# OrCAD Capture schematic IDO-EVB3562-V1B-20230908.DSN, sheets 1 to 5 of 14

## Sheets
1 P11. Power: size A4
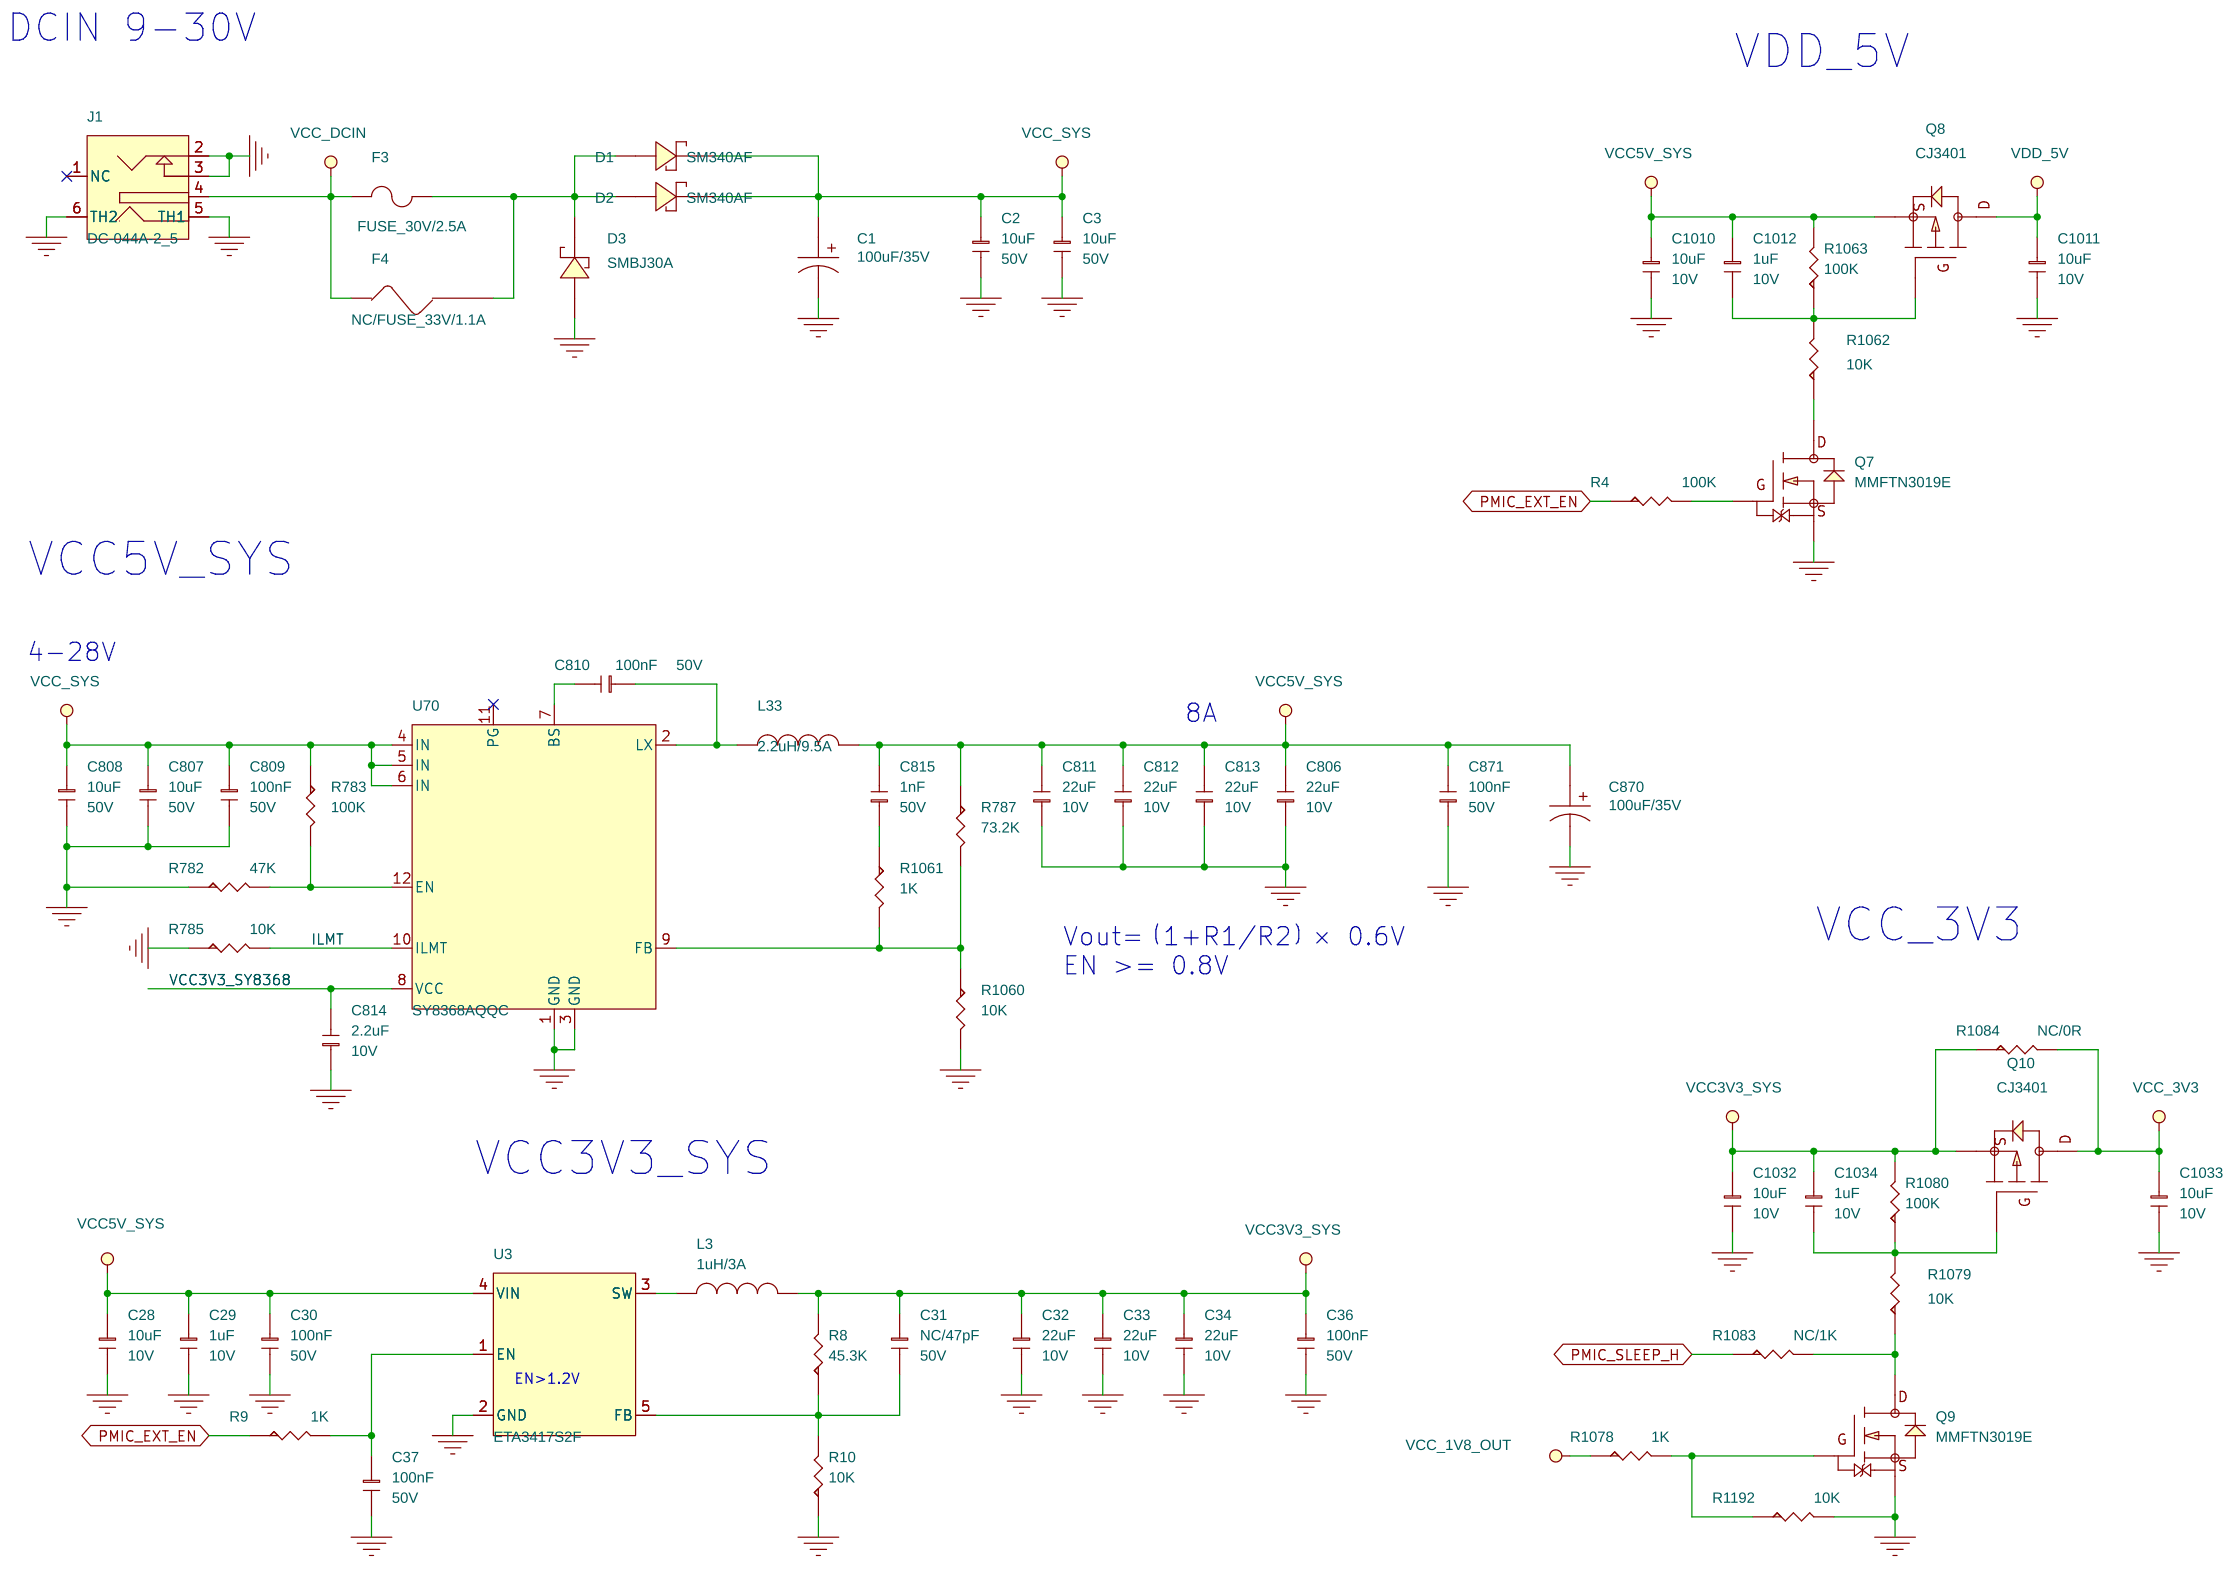
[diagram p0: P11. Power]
2 P12. SOM3562: size A2
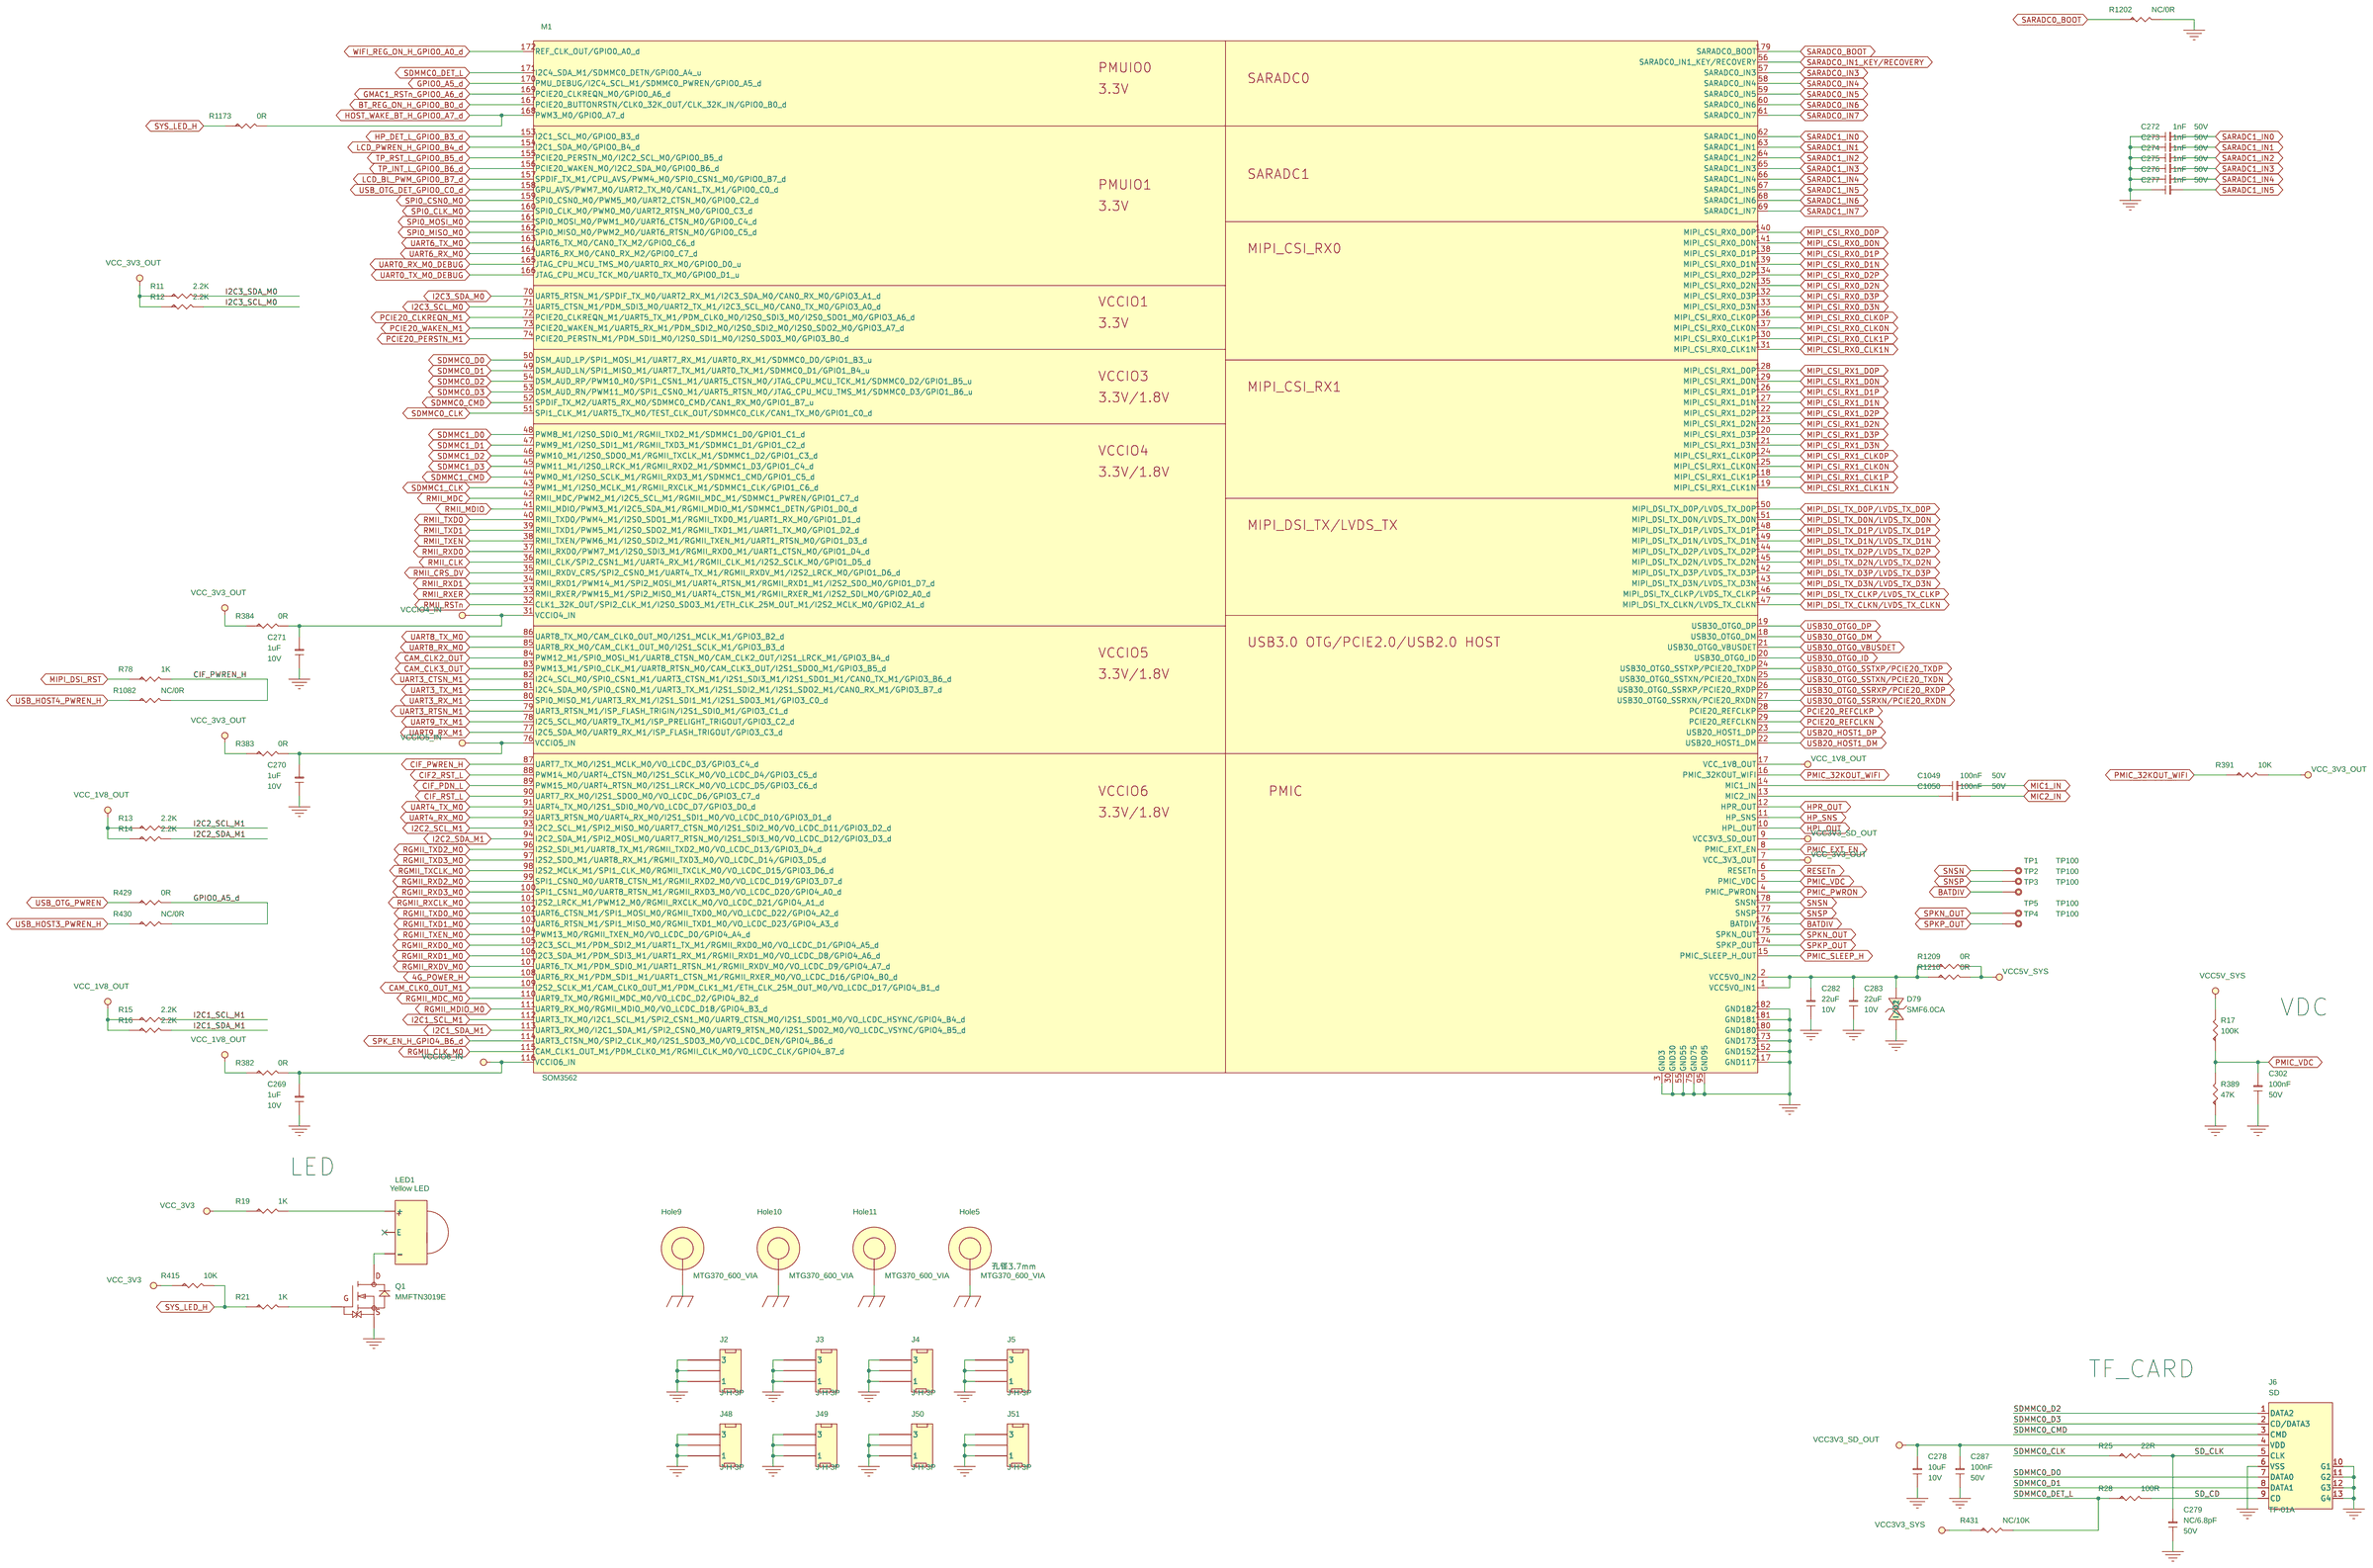
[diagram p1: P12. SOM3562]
3 P13.USB_HUB-FE1.1: size A3; title: IDO-SBC3566-V1B; note: USB_HUB-FE1.1
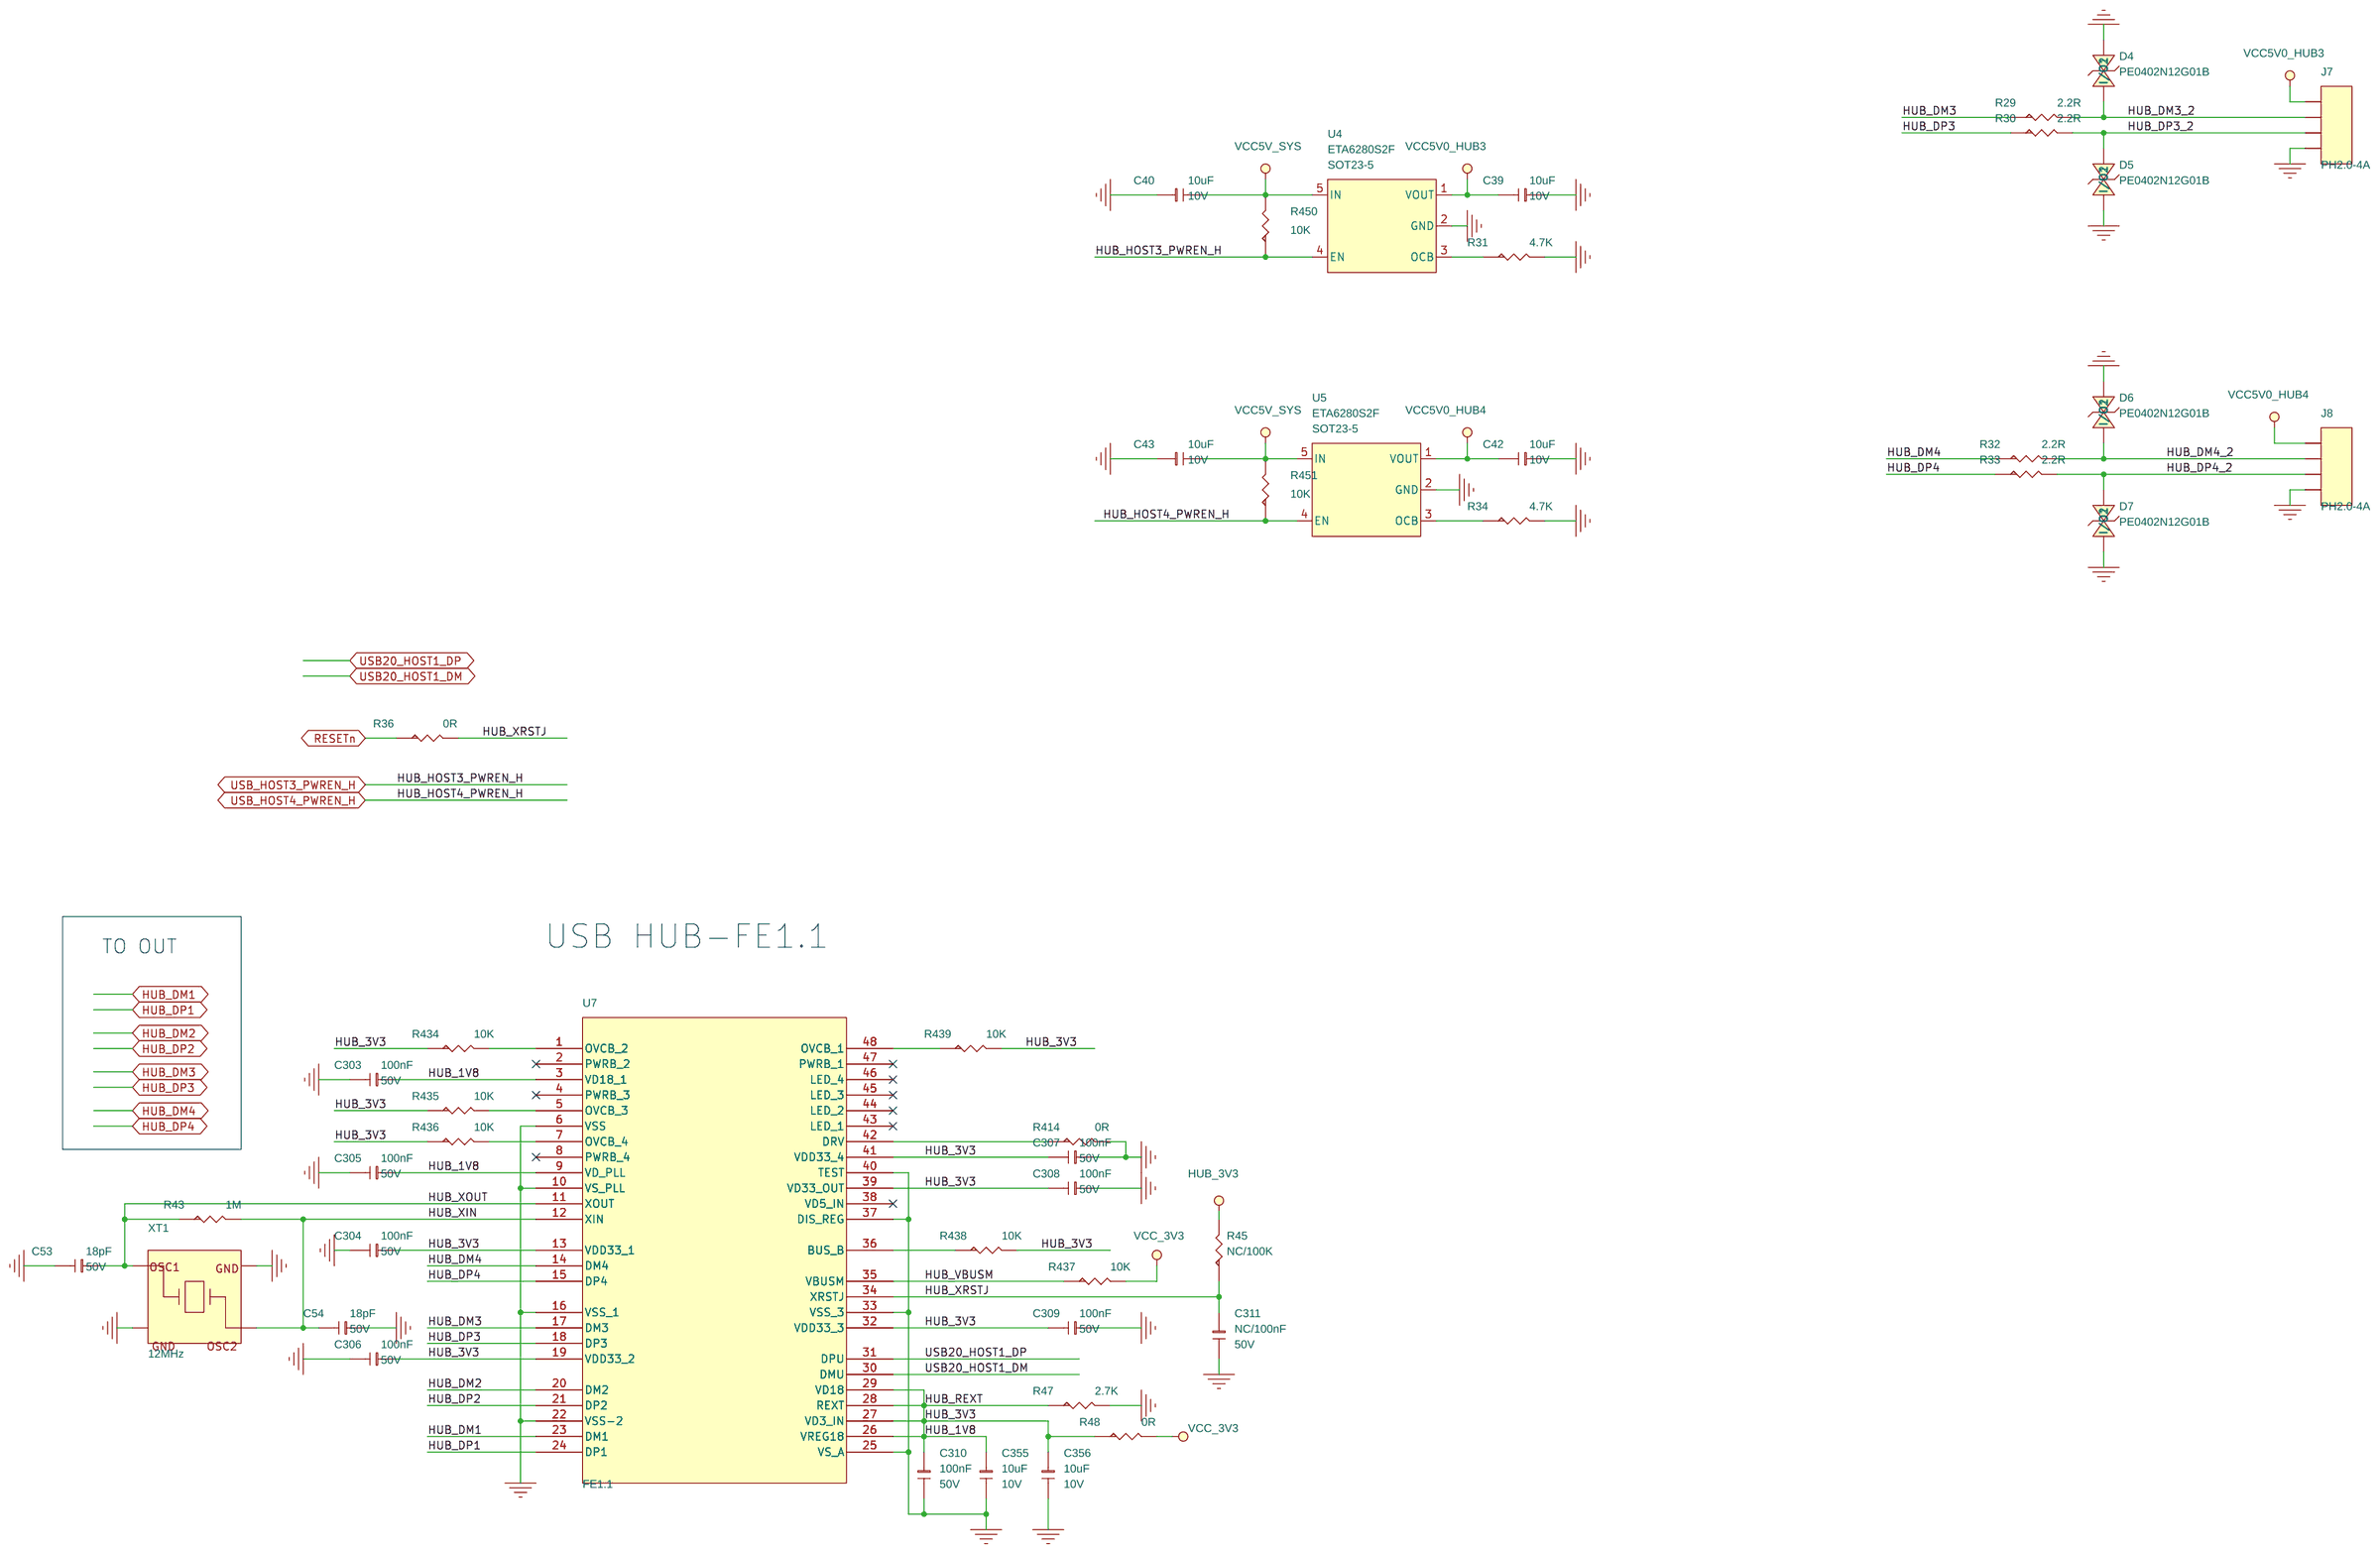
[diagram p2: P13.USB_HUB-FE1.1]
4 P14. 4G-MINI_PCIE: size A3; title: IDO-SBC3566-V1B; note: 4G/5G-MINI_PCIE
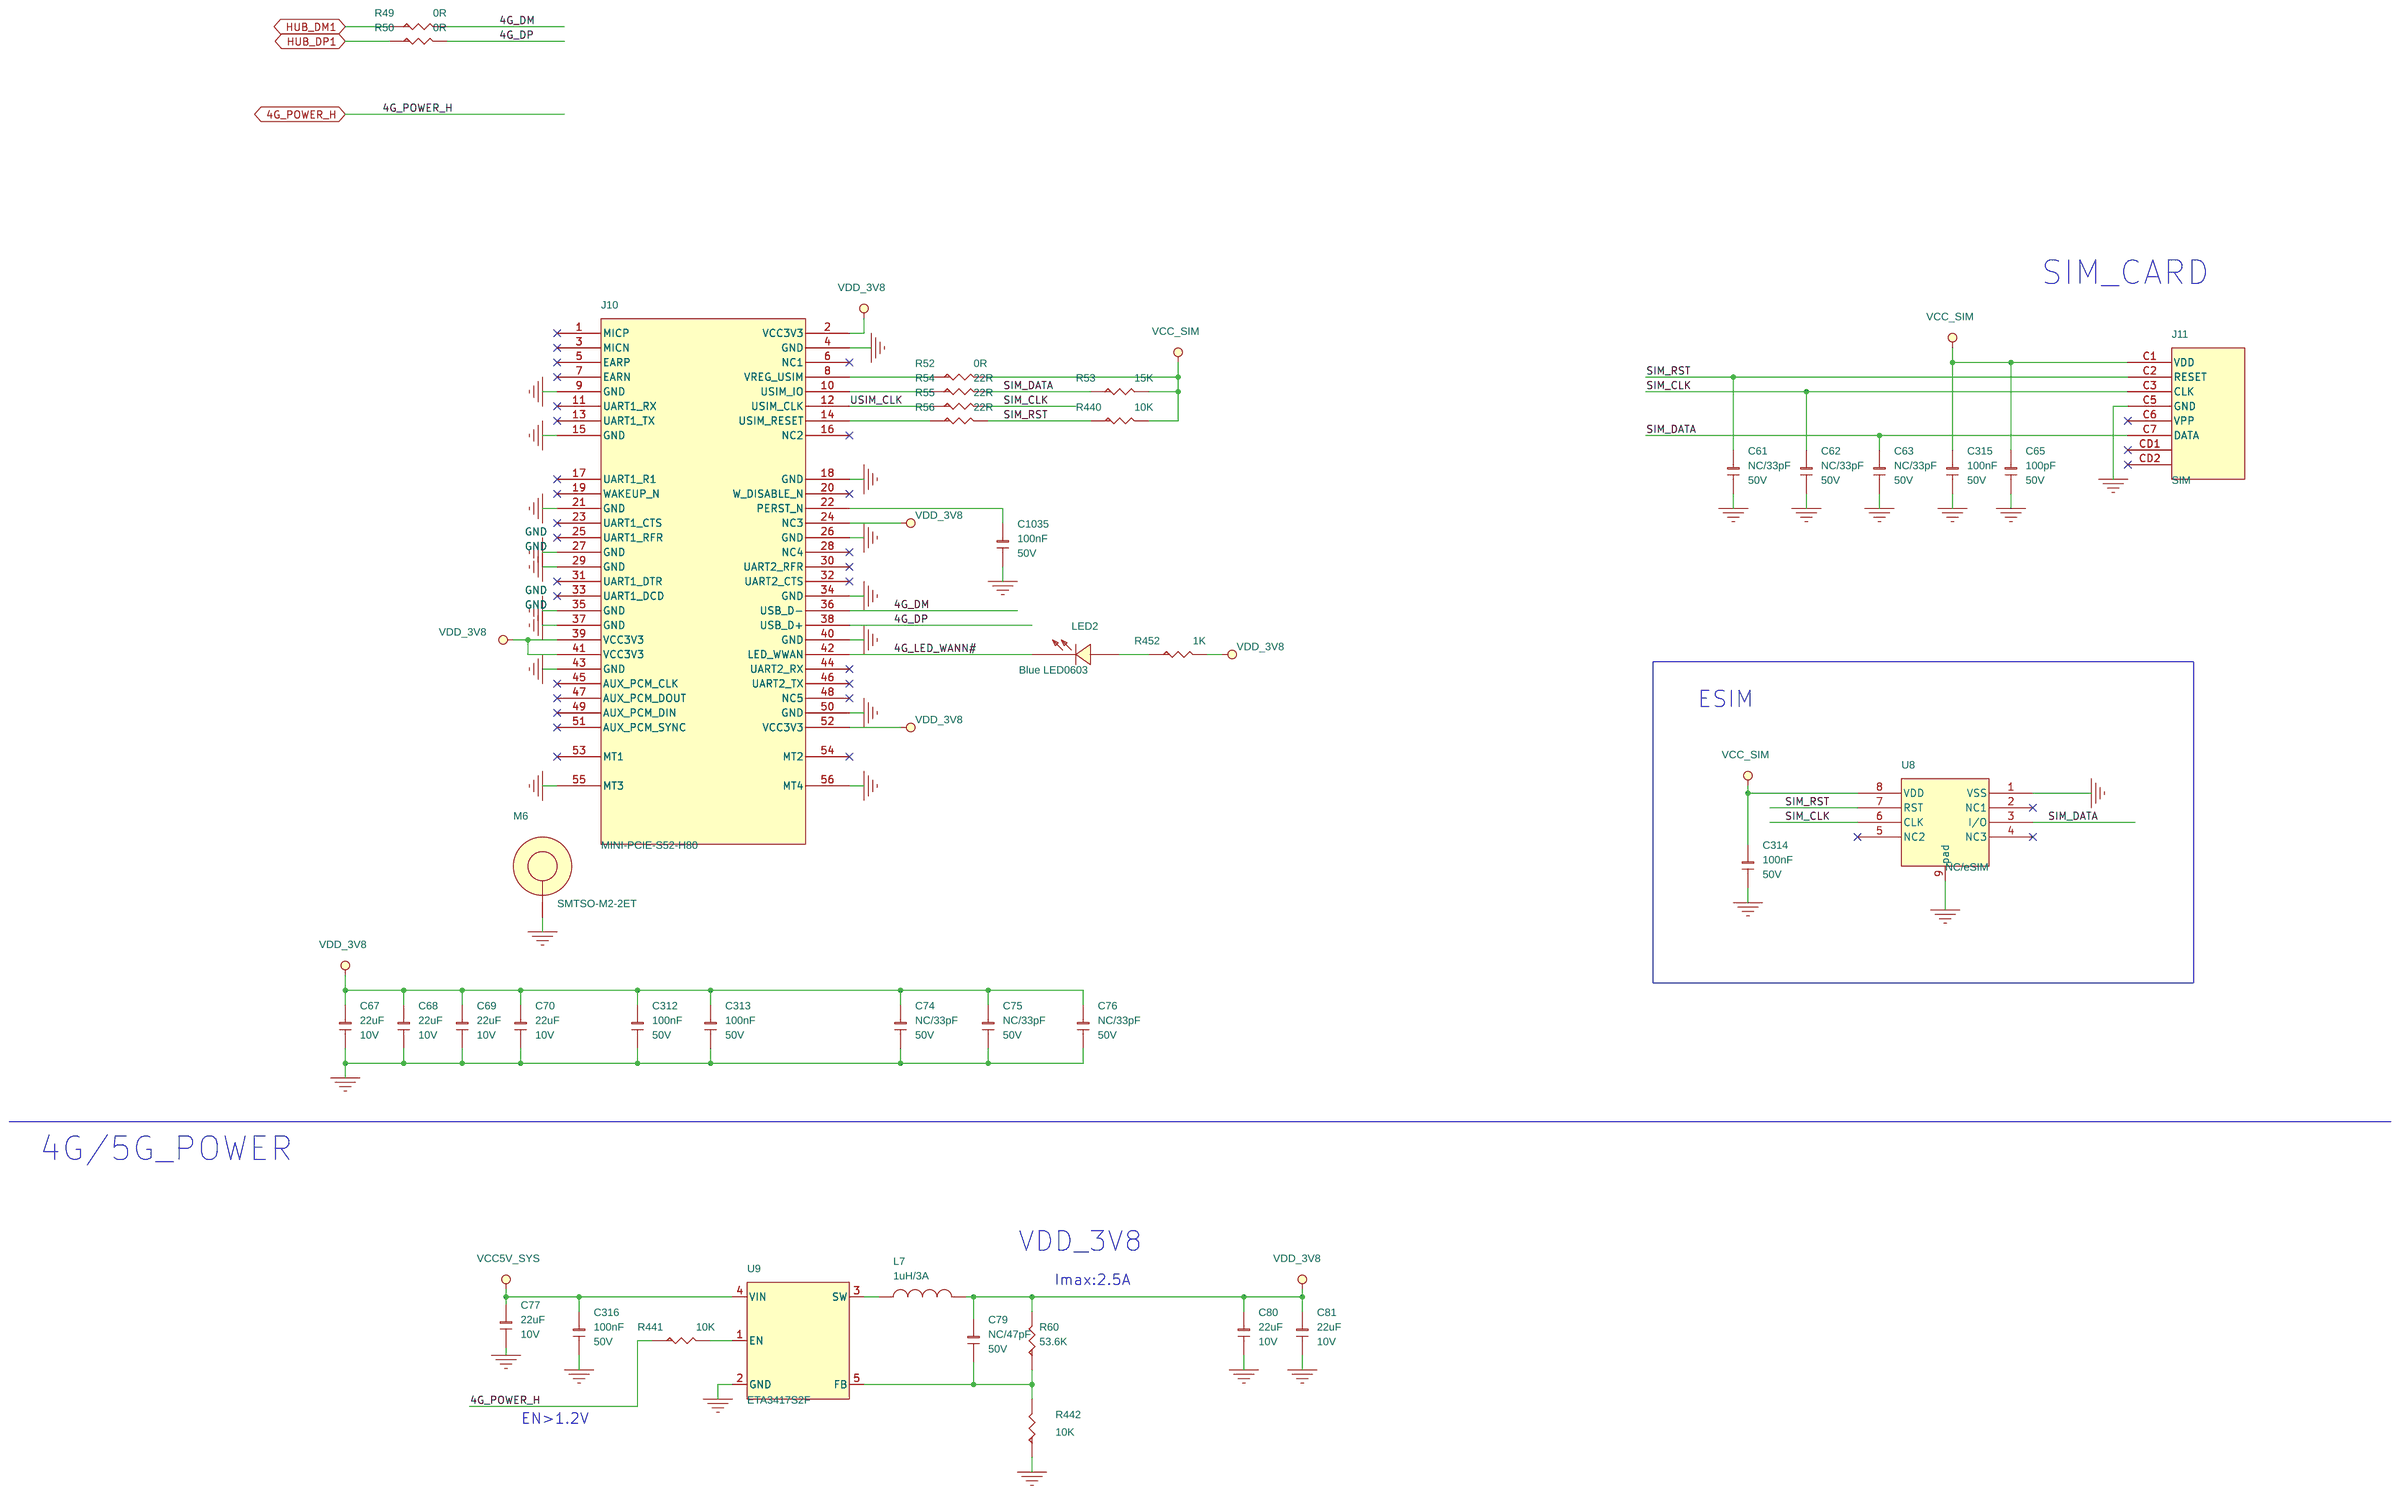
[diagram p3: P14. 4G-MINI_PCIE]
5 P15. VO-LCD: size A3; title: IDO-SBC3566-V1B; note: VO-GM8775C-LVDS
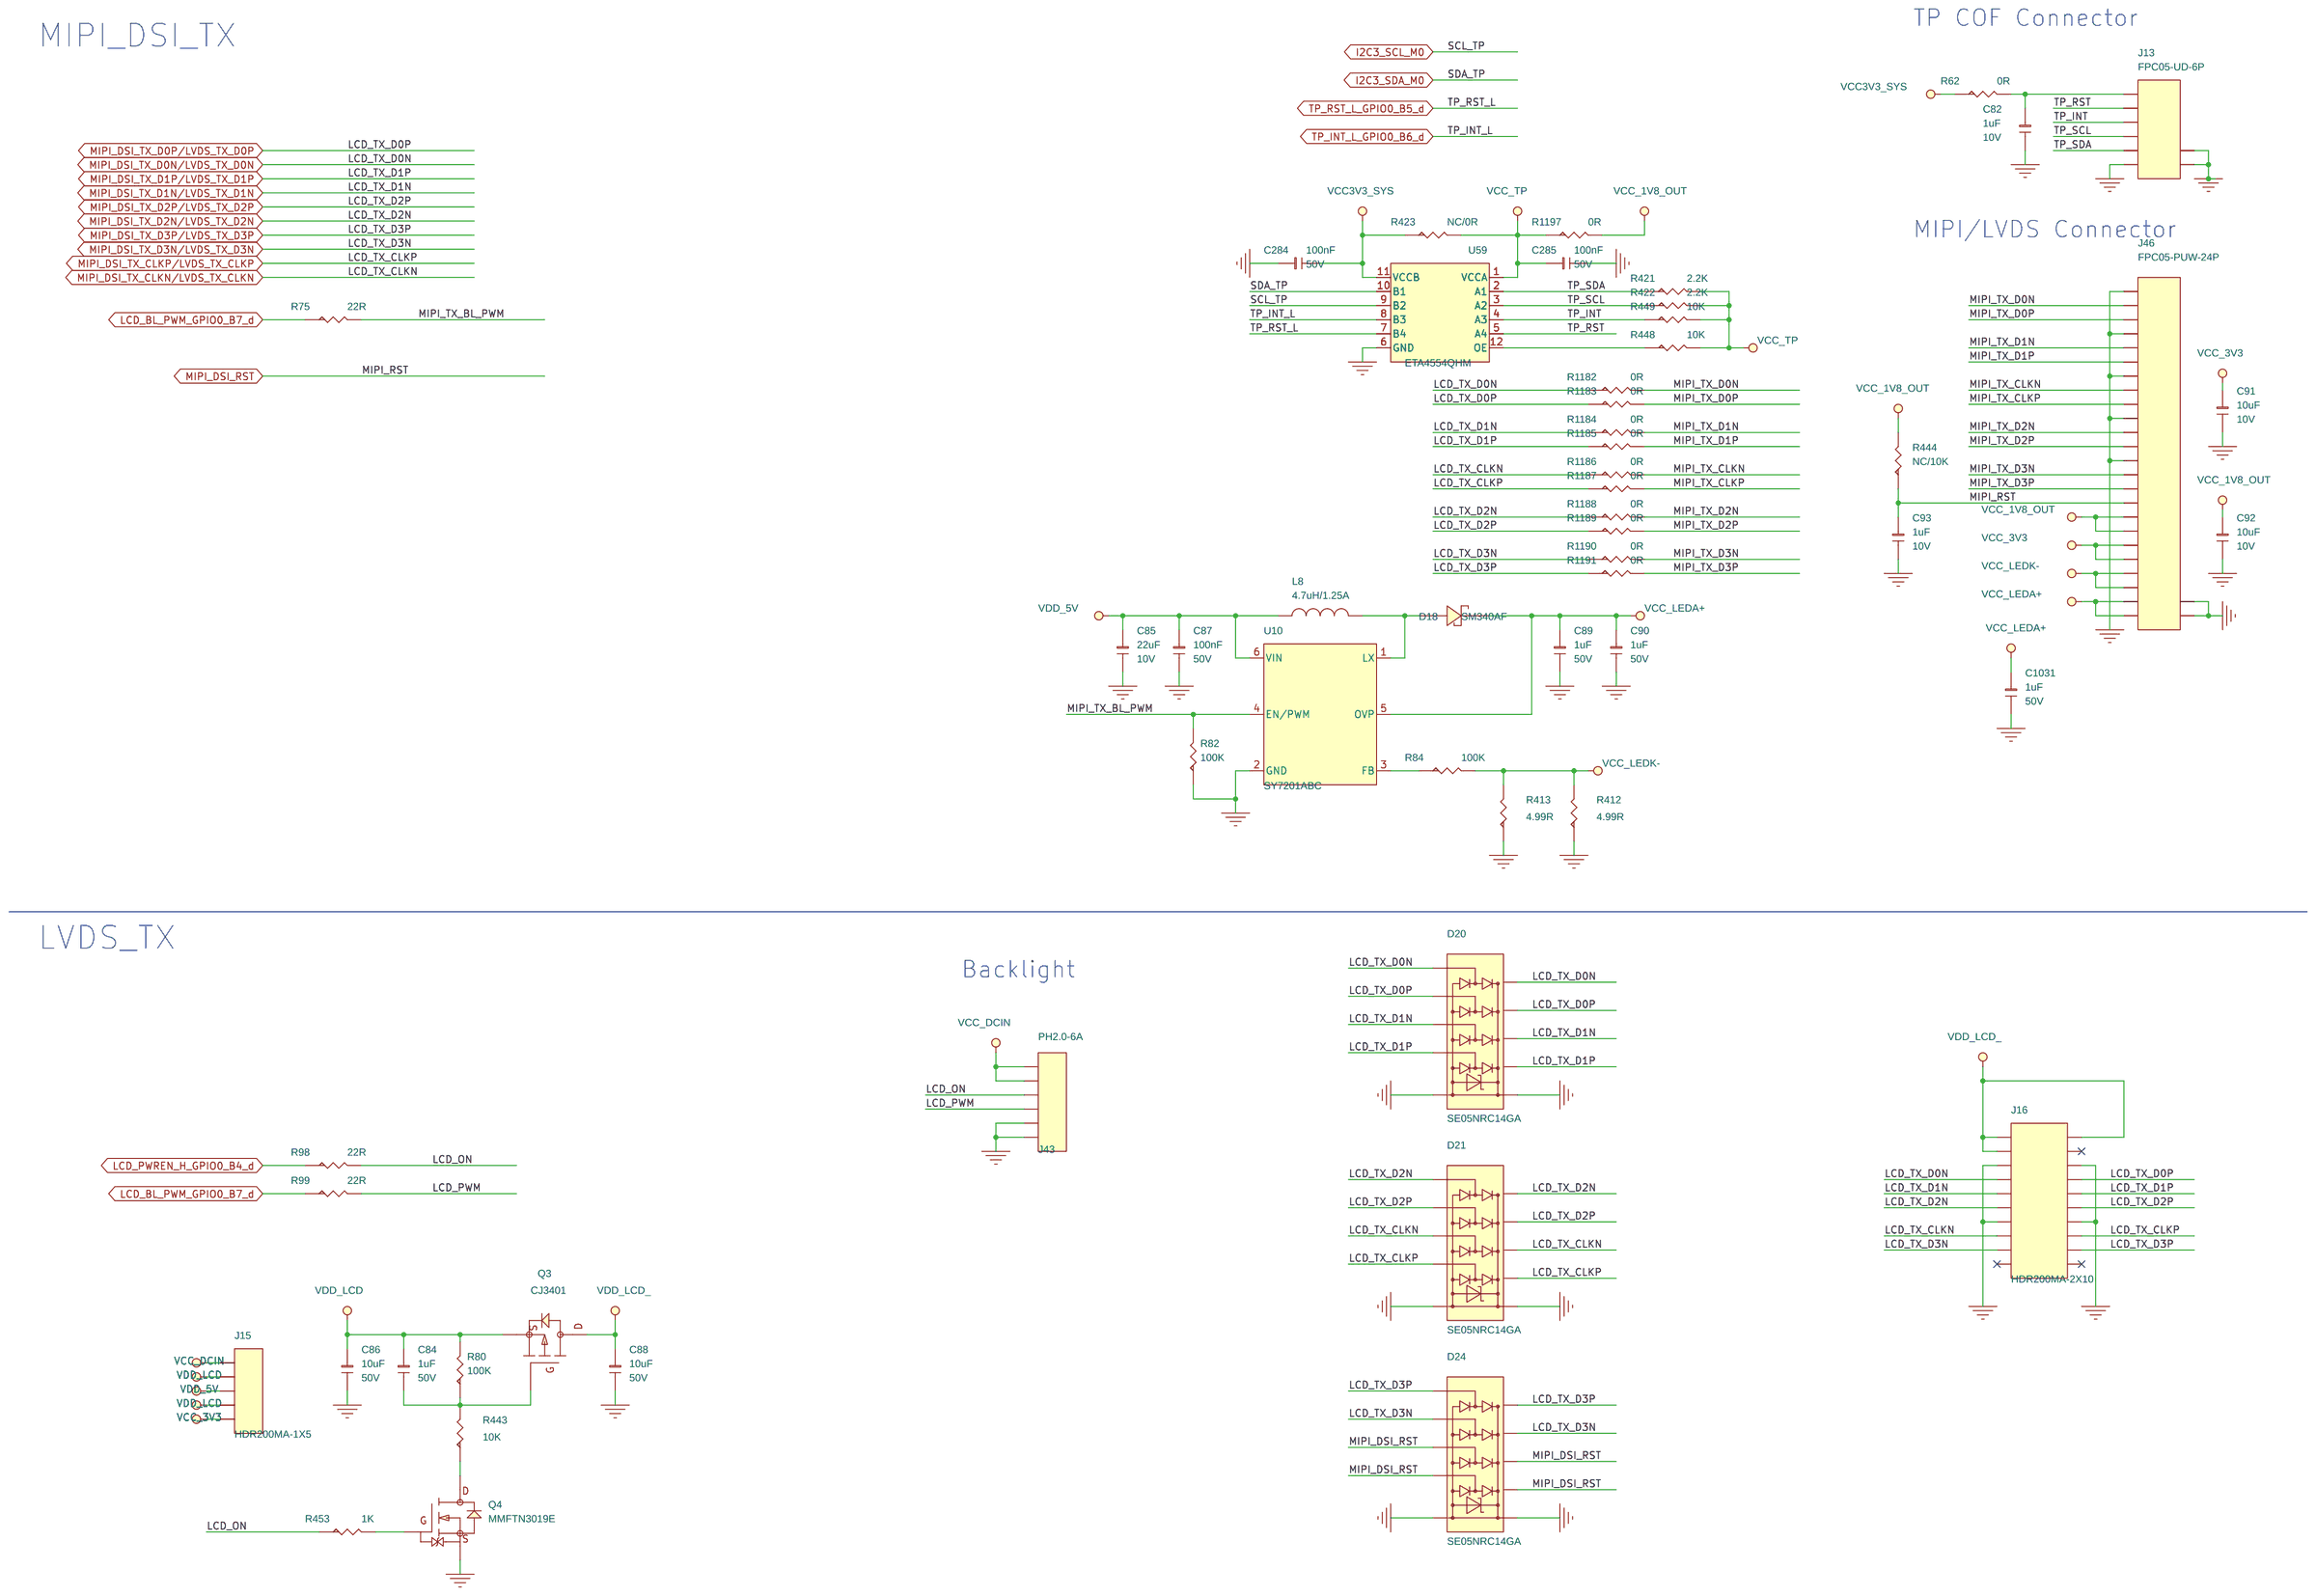
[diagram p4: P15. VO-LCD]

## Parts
sheet P11. Power
C1  100uF/35V  [CAPAE660X770]
C2  10uF  [C1206]
C3  10uF  [C1206]
C28  10uF  [C0603]
C29  1uF  [C0402]
C30  100nF  [C0402]
C31  NC/47pF  [C0402]
C32  22uF  [C0603]
C33  22uF  [C0603]
C34  22uF  [C0603]
C36  100nF  [C0402]
C37  100nF  [C0402]
C806  22uF  [C0805]
C807  10uF  [C1206]
C808  10uF  [C1206]
C809  100nF  [C0402]
C810  100nF  [C0402]
C811  22uF  [C0805]
C812  22uF  [C0805]
C813  22uF  [C0805]
C814  2.2uF  [C0402]
C815  1nF  [C0402]
C870  100uF/35V  [CAPAE660X770]
C871  100nF  [C0402]
C1010  10uF  [C0603]
C1011  10uF  [C0603]
C1012  1uF  [C0402]
C1032  10uF  [C0603]
C1033  10uF  [C0603]
C1034  1uF  [C0402]
D1  SM340AF  [SMAF]
D2  SM340AF  [SMAF]
D3  SMBJ30A  [SMB_DO-214AA]
F3  FUSE_30V/2.5A  [SIP2-10D-510]
F4  NC/FUSE_33V/1.1A  [SMD1812]
J1  DC-044A-2_5  [DC-044A-2_0-DIP]
L3  1uH/3A  [IND_252012]
L33  2.2uH/9.5A  [IND_73x66]
Q7  MMFTN3019E  [SOT523]
Q8  CJ3401  [SOT23]
Q9  MMFTN3019E  [SOT523]
Q10  CJ3401  [SOT23]
R4  100K  [R0402]
R8  45.3K  [R0402]
R9  1K  [R0402]
R10  10K  [R0402]
R782  47K  [R0402]
R783  100K  [R0402]
R785  10K  [R0402]
R787  73.2K  [R0402]
R1060  10K  [R0402]
R1061  1K  [R0402]
R1062  10K  [R0402]
R1063  100K  [R0402]
R1078  1K  [R0402]
R1079  10K  [R0402]
R1080  100K  [R0402]
R1083  NC/1K  [R0402]
R1084  NC/0R  [R0603]
R1192  10K  [R0402]
U3  ETA3417S2F  [SOT23-5]
U70  SY8368AQQC  [QFN3X3-12-SY8368AQQC]
sheet P12. SOM3562
C269  1uF  [C0402]
C270  1uF  [C0402]
C271  1uF  [C0402]
C272  1nF  [C0402]
C273  1nF  [C0402]
C274  1nF  [C0402]
C275  1nF  [C0402]
C276  1nF  [C0402]
C277  1nF  [C0402]
C278  10uF  [C0603]
C279  NC/6.8pF  [C0402]
C282  22uF  [C0603]
C283  22uF  [C0603]
C287  100nF  [C0402]
C302  100nF  [C0402]
C1049  100nF  [C0402]
C1050  100nF  [C0402]
D79  SMF6.0CA  [SOD-123F]
Hole5  MTG370_600_VIA  [MTG370_600_VIA]
Hole9  MTG370_600_VIA  [MTG370_600_VIA]
Hole10  MTG370_600_VIA  [MTG370_600_VIA]
Hole11  MTG370_600_VIA  [MTG370_600_VIA]
J2  J-H-3P  [pbz_icsrc6508sfr]
J3  J-H-3P  [pbz_icsrc6508sfr]
J4  J-H-3P  [pbz_icsrc6508sfr]
J5  J-H-3P  [pbz_icsrc6508sfr]
J6  SD  [TF-01A]
J48  J-H-3P  [pbz_icsrc6508sfr]
J49  J-H-3P  [pbz_icsrc6508sfr]
J50  J-H-3P  [pbz_icsrc6508sfr]
J51  J-H-3P  [pbz_icsrc6508sfr]
LED1  Yellow LED  [LED-SMD_3_2X1_5X1_0]
M1  SOM3562  [SOM3562-182P]
Q1  MMFTN3019E  [SOT523]
R11  2.2K  [R0402]
R12  2.2K  [R0402]
R13  2.2K  [R0402]
R14  2.2K  [R0402]
R15  2.2K  [R0402]
R16  2.2K  [R0402]
R17  100K  [R0402]
R19  1K  [R0402]
R21  1K  [R0402]
R25  22R  [R0402]
R28  100R  [R0402]
R78  1K  [R0402]
R382  0R  [R0402]
R383  0R  [R0402]
R384  0R  [R0402]
R389  47K  [R0402]
R391  10K  [R0402]
R415  10K  [R0402]
R429  0R  [R0402]
R430  NC/0R  [R0402]
R431  NC/10K  [R0402]
R1082  NC/0R  [R0402]
R1173  0R  [R0402]
R1202  NC/0R  [R0603]
R1209  0R  [R0603]
R1210  0R  [R0603]
TP1  TP100  [TP100]
TP2  TP100  [TP100]
TP3  TP100  [TP100]
TP4  TP100  [TP100]
TP5  TP100  [TP100]
sheet P13.USB_HUB-FE1.1
C39  10uF  [C0603]
C40  10uF  [C0603]
C42  10uF  [C0603]
C43  10uF  [C0603]
C53  18pF  [C0402]
C54  18pF  [C0402]
C303  100nF  [C0402]
C304  100nF  [C0402]
C305  100nF  [C0402]
C306  100nF  [C0402]
C307  100nF  [C0402]
C308  100nF  [C0402]
C309  100nF  [C0402]
C310  100nF  [C0402]
C311  NC/100nF  [C0402]
C355  10uF  [C0603]
C356  10uF  [C0603]
D4  PE0402N12G01B  [V0402]
D5  PE0402N12G01B  [V0402]
D6  PE0402N12G01B  [V0402]
D7  PE0402N12G01B  [V0402]
J7  PH2.0-4A  [PH200-4A]
J8  PH2.0-4A  [PH200-4A]
R29  2.2R  [R0402]
R30  2.2R  [R0402]
R31  4.7K  [R0402]
R32  2.2R  [R0402]
R33  2.2R  [R0402]
R34  4.7K  [R0402]
R36  0R  [R0402]
R43  1M  [R0402]
R45  NC/100K  [R0402]
R47  2.7K  [R0402]
R48  0R  [R0402]
R414  0R  [R0402]
R434  10K  [R0402]
R435  10K  [R0402]
R436  10K  [R0402]
R437  10K  [R0402]
R438  10K  [R0402]
R439  10K  [R0402]
R450  10K  [R0402]
R451  10K  [R0402]
U4  ETA6280S2F  [SOT23-5]
U5  ETA6280S2F  [SOT23-5]
U7  FE1.1  [LQFP-48_7x7x05P]
XT1  12MHz  [xtal_32x25_4p]
sheet P14. 4G-MINI_PCIE
C61  NC/33pF  [C0402]
C62  NC/33pF  [C0402]
C63  NC/33pF  [C0402]
C65  100pF  [C0402]
C67  22uF  [C0603]
C68  22uF  [C0603]
C69  22uF  [C0603]
C70  22uF  [C0603]
C74  NC/33pF  [C0402]
C75  NC/33pF  [C0402]
C76  NC/33pF  [C0402]
C77  22uF  [C0603]
C79  NC/47pF  [C0402]
C80  22uF  [C0603]
C81  22uF  [C0603]
C312  100nF  [C0402]
C313  100nF  [C0402]
C314  100nF  [C0402]
C315  100nF  [C0402]
C316  100nF  [C0402]
C1035  100nF  [C0402]
J10  MINI-PCIE-S52-H80  [M_MINIPCIE_SOCKET_CK]
J11  SIM  [SIM-91288-021]
L7  1uH/3A  [IND_252012]
LED2  Blue LED0603  [LED0603]
M6  SMTSO-M2-2ET  [MTG380_620_SMTSO_M2]
R49  0R  [R0402]
R50  0R  [R0402]
R52  0R  [R0402]
R53  15K  [R0402]
R54  22R  [R0402]
R55  22R  [R0402]
R56  22R  [R0402]
R60  53.6K  [R0402]
R440  10K  [R0402]
R441  10K  [R0402]
R442  10K  [R0402]
R452  1K  [R0402]
U8  NC/eSIM  [esim]
U9  ETA3417S2F  [SOT23-5]
sheet P15. VO-LCD
C82  1uF  [C0402]
C84  1uF  [C0603]
C85  22uF  [C0603]
C86  10uF  [C1206]
C87  100nF  [C0402]
C88  10uF  [C1206]
C89  1uF  [C0603]
C90  1uF  [C0603]
C91  10uF  [C0603]
C92  10uF  [C0603]
C93  1uF  [C0402]
C284  100nF  [C0402]
C285  100nF  [C0402]
C1031  1uF  [C0603]
D18  SM340AF  [SMAF]
D20  SE05NRC14GA  [DFN2510-10L]
D21  SE05NRC14GA  [DFN2510-10L]
D24  SE05NRC14GA  [DFN2510-10L]
J13  FPC05-UD-6P  [FPC05-6P]
J15  HDR200MA-1X5  [HDR200MA-1X5]
J16  HDR200MA-2X10  [HDR200MA-2X10]
J43  PH2.0-6A  [PH200-6A]
J46  FPC05-PUW-24P  [FPC05-24P]
L8  4.7uH/1.25A  [IND_252012]
Q3  CJ3401  [SOT23]
Q4  MMFTN3019E  [SOT523]
R62  0R  [R0402]
R75  22R  [R0402]
R80  100K  [R0402]
R82  100K  [R0402]
R84  100K  [R0402]
R98  22R  [R0402]
R99  22R  [R0402]
R412  4.99R  [R0603]
R413  4.99R  [R0603]
R421  2.2K  [R0402]
R422  2.2K  [R0402]
R423  NC/0R  [R0402]
R443  10K  [R0402]
R444  NC/10K  [R0402]
R448  10K  [R0402]
R449  10K  [R0402]
R453  1K  [R0402]
R1182  0R  [R0402]
R1183  0R  [R0402]
R1184  0R  [R0402]
R1185  0R  [R0402]
R1186  0R  [R0402]
R1187  0R  [R0402]
R1188  0R  [R0402]
R1189  0R  [R0402]
R1190  0R  [R0402]
R1191  0R  [R0402]
R1197  0R  [R0402]
U10  SY7201ABC  [SOT23-6]
U59  ETA4554QHM  [ETA4554-QFN12]

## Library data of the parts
C1 C870 = C-AL-SMD: DSC1: ±20%; DSC2: 35V; DSC3: 宽温; DSC4: 2000H; DSC5: -55~105 ℃; DSC6: SMD,6.3x7.7mm; DSC7: CK1V101M-CRE77(ST); ID: 7; Manufacture: 先科|立隆|三莹; Part Name: 贴片铝电容; Part Number: C020302140007; Price: 0.15
C2 C3 C86 C88 C807 C808 = C-1206: DSC1: ±10%; DSC2: 50V; DSC3: X5R; ID: 79; Manufacture: 三星|国巨|村田; Part Name: 贴片电容; Part Number: C020103263826; Price: 0.24
C28 C39 C40 C42 C43 C91 C92 C278 C355 C356 C1010 C1011 C1032 C1033 = C-0603: DSC1: ±20%; DSC2: 10V; DSC3: X5R; ERP Number: 1010200076; ID: 71; Manufacture: 三星|国巨|村田; Part Name: 贴片电容; Part Number: C020102120071; Price: 0.05
C29 C82 C93 C269-C271 C1012 C1034 = C-0402: DSC1: ±10%; DSC2: 10V; DSC3: X5R; ERP Number: 1010200054; ID: 64; Manufacture: 三星|国巨|村田; Part Name: 贴片电容; Part Number: C020102120064; Price: 0.02
C30 C36 C37 C87 C284 C285 C287 C302-C316 C809 C810 C871 C1035 C1049 C1050 = C-0402: DSC1: ±10%; DSC2: 50V; DSC3: X7R; ERP Number: 1010200128; ID: 61; Manufacture: 三星|国巨|村田; Part Name: 贴片电容; Part Number: C020102120061; Price: 0.05
C31 C79 = C-0402: DSC1: ±5%; DSC2: 50V; DSC3: C0G; ERP Number: 1010200213; ID: 36; Manufacture: 三星|国巨|村田; Part Name: 贴片电容; Part Number: C020102120036; Price: 0.01
C32-C34 C67-C70 C77 C80 C81 C85 C282 C283 = C-0603: DSC1: ±20%; DSC2: 10V; DSC3: X5R; ID: 83; Manufacture: 三星|国巨|村田; Part Name: 贴片电容; Part Number: C020107143899; Price: 0.18
C806 C811-C813 = C-0805: DSC1: ±20%; DSC2: 10V; DSC3: X5R; Manufacture: 三星|国巨|村田; Part Name: 贴片电容; Part Number: C020102120075; Price: 0.11
C814 = C-0402: DSC1: ±10%; DSC2: 10V; DSC3: X5R; ID: 66; Manufacture: 三星|国巨|村田; Part Name: 贴片电容; Part Number: C020102120066; Price: 0.02
C272-C277 C815 = C-0402: DSC1: ±10%; DSC2: 50V; DSC3: X7R; ERP Number: 1010200084; ID: 54; Manufacture: 三星|国巨|村田; Part Name: 贴片电容; Part Number: C020102120054; Price: 0.01
D1 D2 D18 = DI-XI-S: DSC1: VR=40V; DSC2: IF=3A; DSC3: VF=500mV/3A; ID: 7; Manufacture: 乐山无线电; Part Name: 肖特基二级管; Part Number: C040202220007; Price: 0.15; Solder: 推荐
D3 = DI-XI-S: DSC1: 单向; DSC2: Vrwm=30V; DSC3: VBR=33V; DSC6: Ppp=600W; ID: 32; Manufacture: 硕凯; Part Name: TVS
F3 = FUSE-RL30-300-SIP2: DSC1: 30V; DSC2: 2.5A; DSC3: SC30-250SW0D; ID: 16; Manufacture: 硕凯; Part Name: 自恢复保险丝; Price: 0.38
F4 = FUSE-SMD1812: DSC1: 33V; DSC2: 1.1A; DSC3: SCF110-33-1812RB; ID: 21; Manufacture: 硕凯; Part Name: 自恢复保险丝; Price: 0.3
J1 = J-DC-044A-2_5: DSC1: 通孔弯针，内径2mm，2.5A，24VDC; DSC2: 11.5*10.1*7.3mm; DSC3: 通孔弯针; DSC4: DC-044A-2.5A-2.0(星坤); DSC5: DC0044A（九龙熹）; ID: 3; Part Name: DC座; Part Number: J100103010003
L3 L7 = L-IND: DSC1: ±20%; DSC2: Isat=3.6A; DSC3: Irms=3A; DSC4: 54mΩ; DSC5: 2.5*2.0*1.2mm; DSC6: WPN252012H1R0MT(顺络); DSC7: FHD252012S-1R0MT(长江微电); DSC8: ZCRH252012-1uH-M(宗成); ID: 52; Manufacture: 宗成|长江微电|顺络; Part Name: 功率电感
L33 = L-IND: DSC1: ±20%; DSC2: Isat=9.5A; DSC3: Irms=6.0A; DSC4: 15mΩ; DSC5: 7.3*6.6*3.0mm; DSC6: MWSA0603S-2R2MT(顺络); ERP Number: 1010200471; ID: 37; Manufacture: 宗成|长江微电|顺络; Part Name: 功率电感; Price: 0.47
Q1 Q4 Q7 Q9 = N-MOS-Q: DSC1: Vds=30V; DSC2: Id=100mA; DSC3: Vgs(th)=1.5V; DSC4: Vgs=±20V; DSC5: pd=150mW; ERP Number: 1010800011; ID: 4; Manufacture: 先科; Part Name: N-MOS; Part Number: C030202190004; Price: 0.1
Q3 Q8 Q10 = P-MOS: DSC1: Vds=-30V; DSC2: Id=-4.2A; DSC3: Vgs(th)=-1.3V; DSC4: Vgs=±12V; DSC5: pd=350mW; ERP Number: 1010800001; ID: 1; Manufacture: 长电; Part Number: C030202190001; Price: 0.17
R4 R17 R45 R80 R82 R84 R783 R1063 R1080 = R-0402: DSC1: ±5%; DSC2: 1/16W; ERP Number: 1010200103; ID: 353; Part Name: 贴片电阻; Part Number: C011002080353; Price: 0.01
R8 = R-0402: DSC1: ±1%; DSC2: 1/16W; ID: 933; Part Name: 贴片电阻; Part Number: C011002080933; Price: 0.01
R9 R19 R21 R452 R453 R1078 R1083 = R-0402: DSC1: ±1%; DSC2: 1/16W; ERP Number: 1010200113; ID: 742; Part Name: 贴片电阻; Part Number: C011002080742; Price: 0.01
R10 R391 R415 R431 R434-R444 R448-R451 R1060 R1062 R1079 R1192 = R-0402: DSC1: ±1%; DSC2: 1/16W; ERP Number: 1010200140; ID: 856; Part Name: 贴片电阻; Part Number: C011002080856; Price: 0.01
R389 R782 = R-0402: DSC1: ±5%; DSC2: 1/16W; ERP Number: 1010200182; ID: 345; Part Name: 贴片电阻; Part Number: C011002080345; Price: 0.01
R785 = R-0402: DSC1: ±5%; DSC2: 1/16W; ERP Number: 1010200096; ID: 328; Part Name: 贴片电阻; Part Number: C011002080328; Price: 0.01
R787 = R-0402: DSC1: ±1%; DSC2: 1/16W; ERP Number: 1010200259; ID: 960; Part Name: 贴片电阻; Part Number: C011002080960; Price: 0.01
R78 R1061 = R-0402: DSC1: ±5%; DSC2: 1/16W; ERP Number: 1010200104; ID: 303; Part Name: 贴片电阻; Part Number: C011002080303; Price: 0.01
R1084 R1202 R1209 R1210 = R-0603: DSC1: ±1%; DSC2: 1/10W; ERP Number: 1010200158; ID: 1,182; Part Name: 贴片电阻; Part Number: C011002081182; Price: 0.01
U3 U9 = U-ETA3417S2F: DSC1: Vi=2.6-7.0V; DSC2: Vo=0.6-7.0V; DSC3: Io=2.5A; DSC4: Vfb=0.6V; DSC6: 3MHz; DSC7: 同步降压; DSC8: 替代料：TI的TLV62569DBVR/矽力杰SY8089AAAC; ID: 43; Manufacture: ETA; Part Name: DCDC; Part Number: C070205183984; Solder: 量产
U70 = U-SY8368AQQC_6: DSC1: Vi=4-28V; DSC2: Vo=0.6~24V; DSC3: I=8A; DSC5: 0.96; DSC6: 800KHz; DSC7: 同步降压; ID: 62; Manufacture: 矽力杰; Part Name: DCDC; Price: 1.69; Solder: 推荐
C279 = C-0402: DSC1: ±0.25PF; DSC2: 50V; DSC3: C0G; ERP Number: 1010200056; ID: 18; Manufacture: 三星|国巨|村田; Part Name: 贴片电容; Part Number: C020102120018; Price: 0.01
D79 = DI-TVS-D: DSC1: 双向; DSC2: Vrwm=6.0V; DSC3: VBR=6.67V; DSC4: Vc=10.3V; DSC5: Ipp=58.3A; DSC6: Ppp=200W; ID: 26; Manufacture: 硕凯; Part Name: TVS
Hole5 Hole9-Hole11 = MH-NOE: DSC1: 顶层和底层焊盘直径=6mm; DSC2: 孔径3.7mm; DSC3: 8个过孔; ID: 33; Part Name: 镀锡(金)焊盘固定孔
J2-J5 J48-J51 = J-H-3P: ID: 12; Part Name: PH
J6 = J-TF-01A: DSC1: 自弹式 MicroSD卡(TF卡) 卡座 外焊 外扣,无弹片 本体最大高度：2mm; DSC3: 贴片; DSC4: KLM-1007（九龙熹）; DSC5: XKTF-N02-N(星坤); ID: 2; Part Name: SD卡座; Part Number: J080102980002
LED1 = D-LED-CT: DSC1: 黄色LED，侧贴，3.2*1.5*1.0mm Right Angle SMD VF=2V; DSC2: E6C1204UYAC1UDA(亿晶源); ID: 11; Part Name: LED; Part Number: C140202660007; Price: 0.12
M1 = SOM3562_3
R11-R16 R421 R422 = R-0402: DSC1: ±1%; DSC2: 1/16W; ID: 778; Part Name: 贴片电阻; Part Number: C011002080778; Price: 0.01
R25 R54-R56 R75 R98 R99 = R-0402: DSC1: ±5%; DSC2: 1/16W; ERP Number: 1010200173; ID: 262; Part Name: 贴片电阻; Part Number: C011002080262; Price: 0.01
R28 = R-0402: DSC1: ±5%; DSC2: 1/16W; ERP Number: 1010200160; ID: 279; Part Name: 贴片电阻; Part Number: C011002080279; Price: 0.01
R62 R382-R384 R423 R1197 = R-0402: DSC1: ±1%; DSC2: 1/16W; ID: 413; Part Name: 贴片电阻; Part Number: C011002080413; Price: 0.01
R36 R48-R50 R52 R414 R429 R430 R1082 R1173 R1182-R1191 = R-0402: DSC1: ±5%; DSC2: 1/16W; ERP Number: 1010200100; ID: 217; Part Name: 贴片电阻; Part Number: C011002080217; Price: 0.01
TP1-TP5 = TP-TEST: DSC1: 焊盘1mm; DSC2: 无孔; DSC3: 圆形; DSC4: 单面; ID: 3; Part Name: 测试点
C53 C54 = C-0402: DSC1: ±5%; DSC2: 50V; DSC3: C0G; ERP Number: 1010200091; ID: 27; Manufacture: 三星|国巨|村田; Part Name: 贴片电容; Part Number: C020102120027; Price: 0.02
D4-D7 = DI-ESD: DSC1: 双向; DSC2: Vdc=12V; DSC4: Vc=40V; DSC5: Cj=0.05pF; ID: 1; Manufacture: 硕凯; Part Name: ESD; Part Number: C040504013980; Price: 0.06; Solder: 推荐
J7 J8 = J-H-4P: DSC1: 4p; DSC2: 2.0mm间距; DSC3: 通孔180度直针; DSC4: 米黄色胶壳 耐高温; DSC5: JLX-PH20-4A（九龙熹）; DSC6: X2016WV-04-46SN(星坤); ID: 13; Part Name: PH; Part Number: J020302820003
R29 R30 R32 R33 = R-0402: DSC1: ±5%; DSC2: 1/16W; ERP Number: 1010200263; ID: 238; Part Name: 贴片电阻; Part Number: C011002080238; Price: 0.01
R31 R34 = R-0402: DSC1: ±5%; DSC2: 1/16W; ERP Number: 1010200177; ID: 320; Part Name: 贴片电阻; Part Number: C011002080320; Price: 0.01
R43 = R-0402: DSC1: ±5%; DSC2: 1/16W; ERP Number: 1010200167; ID: 378; Part Name: 贴片电阻; Part Number: C011002080378; Price: 0.01
R47 = R-0402: DSC1: ±5%; DSC2: 1/16W; ID: 313; Part Name: 贴片电阻; Part Number: C011002080313; Price: 0.01
U4 U5 = U-SY6280AAC: DSC1: 低能耗电源开关; DSC2: 2.4-5.5V 2A; DSC3: 80mA; DSC4: -40~85℃; ID: 1; Manufacture: ETA; Part Name: 功率开关; Price: 0.42
U7 = U-FE1_1: DSC1: USB 2.0 HIGH SPEED 4-PORT HUB CONTROLLER; DSC2: LQFP48,7mm×7mm,0.5mm Pitch; DSC3: 0℃~+70℃; ID: 48; Manufacture: Terminus; Part Name: USB芯片; Part Number: C100209113928
XT1 = XTAL-4P_1: DSC1: 100Ω; DSC2: ±10ppm; DSC3: 12pF; DSC4: -40℃~+85℃; DSC5: 3.2*2.5mm 4P; ERP Number: 1010700002; ID: 4; Manufacture: 泰晶; Part Name: 贴片无源晶振; Part Number: C050102290004; Price: 0.45
C61-C63 C74-C76 = C-0402: DSC1: ±5%; DSC2: 50V; DSC3: C0G; ERP Number: 1010200087; ID: 33; Manufacture: 三星|国巨|村田; Part Name: 贴片电容; Part Number: C020102120033; Price: 0.01
C65 = C-0402: DSC1: ±5%; DSC2: 50V; DSC3: C0G; ERP Number: 1010200152; ID: 40; Manufacture: 三星|国巨|村田; Part Name: 贴片电容; Part Number: C020102120040; Price: 0.01
J10 = J-MINIPCIE-52P_0: DSC1: miniPCIE座子 H=8.0mm; DSC2: 52P; DSC3: 贴片; DSC4: 91304-80-052R2(UMaxconn); ID: 3; Part Name: 金手指连接器; Part Number: J050102900003
J11 = J-SIM-021: DSC1: 抽屉式 MiniSIM卡 卡座 8p; DSC2: 31.0*25.1*26mm; DSC3: 贴片; DSC4: SIM-9036P（九龙熹）; DSC5: XKSIM-816-P8(星坤); ERP Number: 1040100109; ID: 5; Part Name: SIM卡座; Part Number: J080202990002
LED2 = D-LED0603: DSC1: 蓝色LED，SMD,0603，VF=3V; DSC2: NCD0603B1(国星光电); DSC3: 19-217/BHC-ZL1M2RY/3T(亿光); ERP Number: 1010200068; ID: 8; Part Name: LED; Part Number: C140202660004; Price: 0.08
M6 = MH-NOE: DSC1: PCB螺母; ID: 41; Part Name: PCB螺母
R53 = R-0402: DSC1: ±5%; DSC2: 1/16W; ERP Number: 1010200258; ID: 332; Part Name: 贴片电阻; Part Number: C011002080332; Price: 0.01
R60 = R-0402: DSC1: ±1%; DSC2: 1/16W; ID: 943; Part Name: 贴片电阻; Part Number: C011002080943; Price: 0.01
U8 = eSIM
C84 C89 C90 C1031 = C-0603: DSC1: ±10%; DSC2: 50V; DSC3: X5R; ERP Number: 1010200142; ID: 69; Manufacture: 三星|国巨|村田; Part Name: 贴片电容; Part Number: C020102120069; Price: 0.04
D20 D21 D24 = DI-ESD-SE05NRC14GA: DSC1: 双向; DSC2: Vdc=5V; DSC3: Vbr=8V; DSC4: Vc=20V; DSC5: Cj=0.4pF; ID: 8; Manufacture: 硕凯; Part Name: ESD; Part Number: C040504013981; Price: 0.15; Solder: 推荐
J13 = J-FPC-6P: DSC1: 6P; DSC2: 0.5mm间距; DSC3: 双面触点 前插后压 卧贴; DSC4: H=2mm; DSC5: 镀锡; DSC6: X05A20H06T（星坤）; ID: 41; Part Name: FPC座
J15 = J-HDR-5: DSC1: 单排单塑; DSC2: 1x5; DSC3: 2mm脚距; DSC4: 通孔直针; DSC5: 针长8.8mm  2.8+2(H塑高)+4 mm; DSC6: 黑胶; DSC7: X4611WV-05I-C28D40（星坤）; ID: 82; Part Name: 单排针; Part Number: J010203194650
J16 = J-HDR-D-20: DSC1: 双排单塑; DSC2: 2x10; DSC3: 2mm脚距; DSC4: 通孔直针; DSC5: 针长8.8mm  2.8+2(H塑高)+4 mm; DSC6: 黑胶; DSC7: X4621WV-2x10I-C28D40（星坤）; ID: 9; Part Name: 双排针; Part Number: J010102760009
J43 = J-H-6P: DSC1: 6p; DSC2: 2.0mm间距; DSC3: 通孔180度直针; DSC4: 红色胶壳 耐高温; DSC5: A2001WV-6P-1-RD(CJT); ID: 80; Part Name: PH
J46 = J-FPC-24P: DSC1: 24P; DSC2: 0.5mm间距; DSC3: 上接 抽拉式 卧贴; DSC4: H=2mm; DSC5: 镀锡; DSC6: X05B20U24T(星坤); ID: 34; Part Name: FPC座; Part Number: J030102870021
L8 = L-IND: DSC1: ±20%; DSC2: Isat=1.6A; DSC3: Irms=1.25A; DSC4: 260mΩ; DSC5: 2.5*2.0*1.2mm; DSC6: WPN252012H4R7MT(顺络); DSC7: FHD252012S-4R7MT(长江微电); DSC8: ZCRH252012-4.7uH-M(宗成); ID: 54; Manufacture: 宗成|长江微电|顺络; Part Name: 功率电感
R412 R413 = R-0603: DSC1: ±1%; DSC2: 1/10W; ID: 1,238; Part Name: 贴片电阻; Part Number: C011002081238; Price: 0.01
U10 = U-SY7201ABC: DSC1: Vi=2.5-30V; DSC2: Vo=30V; DSC3: Io=2A; DSC4: Vfb=200mV; DSC5: 0.9; DSC6: 1MHz; DSC7: Boost LED驱动; ERP Number: 1010100053; ID: 24; Manufacture: 矽力杰; Part Name: DCDC; Part Number: C070202410024; Price: 1; Solder: 量产
U59 = U-ETA4554QHM: DSC1: 4位 高速缓冲 24Mbps VCC=1.65V-5.5V; DSC2: QFN12; DSC3: -40℃~+85℃; ID: 11; Manufacture: ETA 钰泰; Part Name: 逻辑缓冲器; Part Number: C080105124705; Price: 0.8

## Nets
GND: C1.2 C2.1 C3.1 C28.1 C29.1 C30.1 C32.1 C33.1 C34.1 C36.1 C37.1 C39.2 C40.2 C42.2 C43.2 C53.1 C54.2 C61.1 C62.1 C63.1 C65.1 C67.1 C68.1 C69.1 C70.1 C74.1 C75.1 C76.1 C77.1 C80.1 C81.1 C82.1 C85.1 C86.1 C87.1 C88.1 C89.1 C90.1 C91.1 C92.1 C93.1 C269.1 C270.1 C271.1 C272.1 C273.1 C274.1 C275.1 C276.1 C277.1 C278.1 C279.1 C282.1 C283.1 C284.2 C285.1 C287.1 C302.1 C303.1 C304.1 C305.1 C306.1 C307.2 C308.2 C309.2 C310.1 C311.1 C312.1 C313.1 C314.1 C315.1 C316.1 C355.1 C356.1 C806.2 C807.1 C808.1 C809.1 C811.2 C812.2 C813.2 C814.2 C870.2 C871.2 C1010.1 C1011.1 C1031.1 C1032.1 C1033.1 C1035.1 D3.A D4.1(I/O2) D5.2(I/O1) D6.1(I/O2) D7.2(I/O1) D20.3 D20.8 D21.3 D21.8 D24.3 D24.8 D79.C(I/O1) J1.2 J1.3 J1.5(TH1) J1.6(TH2) J2.1(3) J2.2 J2.3(1) J3.1(3) J3.2 J3.3(1) J4.1(3) J4.2 J4.3(1) J5.1(3) J5.2 J5.3(1) J6.6(VSS) J6.10(G1) J6.11(G2) J6.12(G3) J6.13(G4) J7.4 J8.4 J10.4(GND) J10.9(GND) J10.15(GND) J10.18(GND) J10.21(GND) J10.26(GND) J10.27(GND) J10.29(GND) J10.34(GND) J10.35(GND) J10.37(GND) J10.40(GND) J10.43(GND) J10.50(GND) J10.55(MT3) J10.56(MT4) J11.C5(GND) J13.6 J13.7 J13.8 J16.5 J16.6 J16.13 J16.14 J43.1 J43.2 J46.1 J46.4 J46.7 J46.10 J46.13 J46.25 J46.26 J48.1(3) J48.2 J48.3(1) J49.1(3) J49.2 J49.3(1) J50.1(3) J50.2 J50.3(1) J51.1(3) J51.2 J51.3(1) M1.3(GND3) M1.30(GND30) M1.55(GND55) M1.75(GND75) M1.95(GND95) M1.117(GND117) M1.152(GND152) M1.173(GND173) M1.180(GND180) M1.181(GND181) M1.182(GND182) M6.1 Q1.2(SOURCE) Q4.2(SOURCE) Q7.2(SOURCE) Q9.2(SOURCE) R10.1 R31.2 R34.2 R47.2 R82.1 R389.1 R412.1 R413.1 R414.2 R442.1 R782.1 R785.1 R1060.2 R1192.2 R1202.2 U3.2(GND) U4.2(GND) U5.2(GND) U7.6(VSS) U7.10(VS_PLL) U7.16(VSS_1) U7.22(VSS-2) U7.25(VS_A) U7.33(VSS_3) U7.37(DIS_REG) U7.40(TEST) U8.1(VSS) U8.9(pad) U9.2(GND) U10.2(GND) U59.6(GND) U70.1(GND) U70.3(GND) XT1.2 XT1.4 ; also on sheet 6 7 8 9 10 11 12 13 14
GND_EARTH: Hole5.1 Hole9.1 Hole10.1 Hole11.1 ; also on sheet 7 8 11
VCC3V3_SD_OUT: C278.2 C287.2 J6.4(VDD) M1.9(VCC3V3_SD_OUT)
VCC3V3_SY8368: C814.1 U70.8(VCC)
VCC3V3_SYS: C31.2 C32.2 C33.2 C34.2 C36.2 C284.1 C1032.2 C1034.2 L3.2 Q10.2(SOURCE) R8.2 R62.1 R423.1 R431.1 R1080.2 R1084.1 U59.11(VCCB) ; also on sheet 13 14
VCC5V0_HUB3: C39.1 J7.1 U4.1(VOUT)
VCC5V0_HUB4: C42.1 J8.1 U5.1(VOUT)
VCC5V_SYS: C28.2 C29.2 C30.2 C40.1 C43.1 C77.2 C316.2 C806.1 C811.1 C812.1 C813.1 C815.1 C870.1 C871.1 C1010.2 C1012.2 L33.2 Q8.2(SOURCE) R17.2 R450.2 R451.2 R787.1 R1063.2 R1209.2 R1210.2 U3.4(VIN) U4.5(IN) U5.5(IN) U9.4(VIN) ; also on sheet 10
VCC_1V8_OUT: C92.2 J46.17 J46.18 M1.17(VCC_1V8_OUT) R13.1 R14.1 R15.1 R16.1 R382.1 R444.2 R1078.1 R1197.2
VCC_3V3: C91.2 C1033.2 J15.5 J46.19 J46.20 Q10.3(DRAIN) R19.1 R48.2 R415.1 R437.2 R1084.2 ; also on sheet 6 7 8 9 11 12 14
VCC_3V3_OUT: M1.7(VCC_3V3_OUT) R11.1 R12.1 R383.1 R384.1 R391.2
VCC_DCIN: F3.1 F4.1 J1.4 J15.1 J43.5 J43.6
VCC_LEDA+: C89.2 C90.2 C1031.2 D18.C J46.23 J46.24 U10.5(OVP)
VCC_LEDK-: J46.21 J46.22 R84.2 R412.2 R413.2
VCC_SIM: C65.2 C314.2 C315.2 J11.C1(VDD) R52.2 R53.2 R440.2 U8.8(VDD)
VCC_SYS: C1.1 C2.2 C3.2 C807.2 C808.2 C809.2 D1.C D2.C R783.1 U70.4(IN) U70.5(IN) U70.6(IN)
VCC_TP: C285.2 R421.2 R422.2 R423.2 R448.2 R449.2 R1197.1 U59.1(VCCA)
VCCIO4_IN: C271.2 M1.31(VCCIO4_IN) R384.2
VCCIO5_IN: C270.2 M1.76(VCCIO5_IN) R383.2
VCCIO6_IN: C269.2 M1.116(VCCIO6_IN) R382.2
VDD_3V8: C67.2 C68.2 C69.2 C70.2 C74.2 C75.2 C76.2 C79.2 C80.2 C81.2 C312.2 C313.2 J10.2(VCC3V3) J10.24(NC3) J10.39(VCC3V3) J10.41(VCC3V3) J10.52(VCC3V3) L7.2 R60.2 R452.2
VDD_5V: C85.2 C87.2 C1011.2 J15.3 L8.1 Q8.3(DRAIN) U10.6(VIN) ; also on sheet 9 12
VDD_LCD: C84.2 C86.2 J15.2 J15.4 Q3.2(SOURCE) R80.2
VDD_LCD_: C88.2 J16.1 J16.2 J16.3 Q3.3(DRAIN)
4G_DM: J10.36(USB_D-) R49.2
4G_DP: J10.38(USB_D+) R50.2
4G_LED_WANN#: J10.42(LED_WWAN) LED2.C(CATHODE)
4G_POWER_H: M1.108(UART6_RX_M1/PDM_SDI1_M1/UART1_CTSN_M1/RGMII_RXER_M0/VO_LCDC_D16/GPIO4_B0_d) R441.1
BATDIV: M1.176(BATDIV) TP3.1
BT_REG_ON_H_GPIO0_B0_d: M1.167(PCIE20_BUTTONRSTN/CLK0_32K_OUT/CLK_32K_IN/GPIO0_B0_d) ; also on sheet 13
CAM_CLK0_OUT_M1: M1.109(I2S2_SCLK_M1/CAM_CLK0_OUT_M1/PDM_CLK1_M1/ETH_CLK_25M_OUT_M0/VO_LCDC_D17/GPIO4_B1_d) ; also on sheet 6
CAM_CLK2_OUT: M1.84(PWM12_M1/SPI0_MOSI_M1/UART8_CTSN_M0/CAM_CLK2_OUT/I2S1_LRCK_M1/GPIO3_B4_d) ; also on sheet 6
CAM_CLK3_OUT: M1.83(PWM13_M1/SPI0_CLK_M1/UART8_RTSN_M0/CAM_CLK3_OUT/I2S1_SDO0_M1/GPIO3_B5_d) ; also on sheet 6
CIF2_RST_L: M1.88(PWM14_M0/UART4_CTSN_M0/I2S1_SCLK_M0/VO_LCDC_D4/GPIO3_C5_d) ; also on sheet 6
CIF_PDN_L: M1.89(PWM15_M0/UART4_RTSN_M0/I2S1_LRCK_M0/VO_LCDC_D5/GPIO3_C6_d) ; also on sheet 6
CIF_PWREN_H: M1.87(UART7_TX_M0/I2S1_MCLK_M0/VO_LCDC_D3/GPIO3_C4_d) R78.2 R1082.2 ; also on sheet 6
CIF_RST_L: M1.90(UART7_RX_M0/I2S1_SDO0_M0/VO_LCDC_D6/GPIO3_C7_d) ; also on sheet 6
GMAC1_RSTn_GPIO0_A6_d: M1.169(PCIE20_CLKREQN_M0/GPIO0_A6_d) ; also on sheet 8
GPIO0_A5_d: M1.170(PMU_DEBUG/I2C4_SCL_M1/SDMMC0_PWREN/GPIO0_A5_d) R429.2 R430.2
HOST_WAKE_BT_H_GPIO0_A7_d: M1.168(PWM3_M0/GPIO0_A7_d) R1173.2 ; also on sheet 13
HP_DET_L_GPIO0_B3_d: M1.153(I2C1_SCL_M0/GPIO0_B3_d) ; also on sheet 12
HP_SNS: M1.11(HP_SNS) ; also on sheet 12
HPL_OUT: M1.10(HPL_OUT) ; also on sheet 12
HPR_OUT: M1.12(HPR_OUT) ; also on sheet 12
HUB_1V8: C303.2 C305.2 C310.2 C355.2 U7.3(VD18_1) U7.9(VD_PLL) U7.26(VREG18) U7.29(VD18)
HUB_3V3: C304.2 C306.2 C307.1 C308.1 C309.1 C356.2 R45.2 R48.1 R434.1 R435.1 R436.1 R438.2 R439.2 U7.13(VDD33_1) U7.19(VDD33_2) U7.27(VD3_IN) U7.32(VDD33_3) U7.39(VD33_OUT) U7.41(VDD33_4)
HUB_DM1: R49.1 U7.23(DM1)
HUB_DM2: U7.20(DM2) ; also on sheet 10
HUB_DM3: R29.1 U7.17(DM3)
HUB_DM3_2: D4.2(I/O1) J7.2 R29.2
HUB_DM4: R32.1 U7.14(DM4)
HUB_DM4_2: D6.2(I/O1) J8.2 R32.2
HUB_DP1: R50.1 U7.24(DP1)
HUB_DP2: U7.21(DP2) ; also on sheet 10
HUB_DP3: R30.1 U7.18(DP3)
HUB_DP3_2: D5.1(I/O2) J7.3 R30.2
HUB_DP4: R33.1 U7.15(DP4)
HUB_DP4_2: D7.1(I/O2) J8.3 R33.2
HUB_REXT: R47.1 U7.28(REXT)
HUB_VBUSM: R437.1 U7.35(VBUSM)
HUB_XIN: C54.1 R43.2 U7.12(XIN) XT1.3
HUB_XOUT: C53.2 R43.1 U7.11(XOUT) XT1.1
HUB_XRSTJ: C311.2 R36.2 R45.1 U7.34(XRSTJ)
I2C1_SCL_M1: M1.112(UART3_TX_M0/I2C1_SCL_M1/SPI2_CSN1_M0/UART9_CTSN_M0/I2S1_SDO1_M0/VO_LCDC_HSYNC/GPIO4_B4_d) R15.2 ; also on sheet 6
I2C1_SDA_M1: M1.113(UART3_RX_M0/I2C1_SDA_M1/SPI2_CSN0_M0/UART9_RTSN_M0/I2S1_SDO2_M0/VO_LCDC_VSYNC/GPIO4_B5_d) R16.2 ; also on sheet 6
I2C2_SCL_M1: M1.93(I2C2_SCL_M1/SPI2_MISO_M0/UART7_CTSN_M0/I2S1_SDI2_M0/VO_LCDC_D11/GPIO3_D2_d) R13.2 ; also on sheet 6
I2C2_SDA_M1: M1.94(I2C2_SDA_M1/SPI2_MOSI_M0/UART7_RTSN_M0/I2S1_SDI3_M0/VO_LCDC_D12/GPIO3_D3_d) R14.2 ; also on sheet 6
I2C3_SCL_M0: M1.71(UART5_CTSN_M1/PDM_SDI3_M0/UART2_TX_M1/I2C3_SCL_M0/CAN0_TX_M0/GPIO3_A0_d) R12.2 U59.9(B2) ; also on sheet 14
I2C3_SDA_M0: M1.70(UART5_RTSN_M1/SPDIF_TX_M0/UART2_RX_M1/I2C3_SDA_M0/CAN0_RX_M0/GPIO3_A1_d) R11.2 U59.10(B1) ; also on sheet 14
ILMT: R785.2 U70.10(ILMT)
LCD_BL_PWM_GPIO0_B7_d: M1.157(SPDIF_TX_M1/CPU_AVS/PWM4_M0/SPI0_CSN1_M0/GPIO0_B7_d) R75.1 R99.1
LCD_ON: J43.4 R98.2 R453.1
LCD_PWM: J43.3 R99.2
LCD_PWREN_H_GPIO0_B4_d: M1.154(I2C1_SDA_M0/GPIO0_B4_d) R98.1
MIC1_IN: C1049.2 ; also on sheet 12
MIC2_IN: C1050.2 ; also on sheet 12
MIPI_CSI_RX0_CLK0N: M1.137(MIPI_CSI_RX0_CLK0N) ; also on sheet 6
MIPI_CSI_RX0_CLK0P: M1.136(MIPI_CSI_RX0_CLK0P) ; also on sheet 6
MIPI_CSI_RX0_CLK1N: M1.131(MIPI_CSI_RX0_CLK1N) ; also on sheet 6
MIPI_CSI_RX0_CLK1P: M1.130(MIPI_CSI_RX0_CLK1P) ; also on sheet 6
MIPI_CSI_RX0_D0N: M1.141(MIPI_CSI_RX0_D0N) ; also on sheet 6
MIPI_CSI_RX0_D0P: M1.140(MIPI_CSI_RX0_D0P) ; also on sheet 6
MIPI_CSI_RX0_D1N: M1.139(MIPI_CSI_RX0_D1N) ; also on sheet 6
MIPI_CSI_RX0_D1P: M1.138(MIPI_CSI_RX0_D1P) ; also on sheet 6
MIPI_CSI_RX0_D2N: M1.135(MIPI_CSI_RX0_D2N) ; also on sheet 6
MIPI_CSI_RX0_D2P: M1.134(MIPI_CSI_RX0_D2P) ; also on sheet 6
MIPI_CSI_RX0_D3N: M1.133(MIPI_CSI_RX0_D3N) ; also on sheet 6
MIPI_CSI_RX0_D3P: M1.132(MIPI_CSI_RX0_D3P) ; also on sheet 6
MIPI_CSI_RX1_CLK0N: M1.125(MIPI_CSI_RX1_CLK0N) ; also on sheet 6
MIPI_CSI_RX1_CLK0P: M1.124(MIPI_CSI_RX1_CLK0P) ; also on sheet 6
MIPI_CSI_RX1_CLK1N: M1.119(MIPI_CSI_RX1_CLK1N)
MIPI_CSI_RX1_CLK1P: M1.118(MIPI_CSI_RX1_CLK1P)
MIPI_CSI_RX1_D0N: M1.129(MIPI_CSI_RX1_D0N) ; also on sheet 6
MIPI_CSI_RX1_D0P: M1.128(MIPI_CSI_RX1_D0P) ; also on sheet 6
MIPI_CSI_RX1_D1N: M1.127(MIPI_CSI_RX1_D1N) ; also on sheet 6
MIPI_CSI_RX1_D1P: M1.126(MIPI_CSI_RX1_D1P) ; also on sheet 6
MIPI_CSI_RX1_D2N: M1.123(MIPI_CSI_RX1_D2N) ; also on sheet 6
MIPI_CSI_RX1_D2P: M1.122(MIPI_CSI_RX1_D2P) ; also on sheet 6
MIPI_CSI_RX1_D3N: M1.121(MIPI_CSI_RX1_D3N) ; also on sheet 6
MIPI_CSI_RX1_D3P: M1.120(MIPI_CSI_RX1_D3P) ; also on sheet 6
MIPI_DSI_RST: C93.2 D24.4 D24.5 D24.6 D24.7 J46.16 R78.1 R444.1
MIPI_DSI_TX_CLKN/LVDS_TX_CLKN: D21.4 D21.7 J16.15 M1.147(MIPI_DSI_TX_CLKN/LVDS_TX_CLKN) R1186.1
MIPI_DSI_TX_CLKP/LVDS_TX_CLKP: D21.5 D21.6 J16.16 M1.146(MIPI_DSI_TX_CLKP/LVDS_TX_CLKP) R1187.1
MIPI_DSI_TX_D0N/LVDS_TX_D0N: D20.1 D20.10 J16.7 M1.151(MIPI_DSI_TX_D0N/LVDS_TX_D0N) R1182.1
MIPI_DSI_TX_D0P/LVDS_TX_D0P: D20.2 D20.9 J16.8 M1.150(MIPI_DSI_TX_D0P/LVDS_TX_D0P) R1183.1
MIPI_DSI_TX_D1N/LVDS_TX_D1N: D20.4 D20.7 J16.9 M1.149(MIPI_DSI_TX_D1N/LVDS_TX_D1N) R1184.1
MIPI_DSI_TX_D1P/LVDS_TX_D1P: D20.5 D20.6 J16.10 M1.148(MIPI_DSI_TX_D1P/LVDS_TX_D1P) R1185.1
MIPI_DSI_TX_D2N/LVDS_TX_D2N: D21.1 D21.10 J16.11 M1.145(MIPI_DSI_TX_D2N/LVDS_TX_D2N) R1188.1
MIPI_DSI_TX_D2P/LVDS_TX_D2P: D21.2 D21.9 J16.12 M1.144(MIPI_DSI_TX_D2P/LVDS_TX_D2P) R1189.1
MIPI_DSI_TX_D3N/LVDS_TX_D3N: D24.2 D24.9 J16.17 M1.143(MIPI_DSI_TX_D3N/LVDS_TX_D3N) R1190.1
MIPI_DSI_TX_D3P/LVDS_TX_D3P: D24.1 D24.10 J16.18 M1.142(MIPI_DSI_TX_D3P/LVDS_TX_D3P) R1191.1
MIPI_TX_BL_PWM: R75.2 R82.2 U10.4(EN/PWM)
MIPI_TX_CLKN: J46.8 R1186.2
MIPI_TX_CLKP: J46.9 R1187.2
MIPI_TX_D0N: J46.2 R1182.2
MIPI_TX_D0P: J46.3 R1183.2
MIPI_TX_D1N: J46.5 R1184.2
MIPI_TX_D1P: J46.6 R1185.2
MIPI_TX_D2N: J46.11 R1188.2
MIPI_TX_D2P: J46.12 R1189.2
MIPI_TX_D3N: J46.14 R1190.2
MIPI_TX_D3P: J46.15 R1191.2
PCIE20_CLKREQN_M1: M1.72(PCIE20_CLKREQN_M1/UART5_TX_M1/PDM_CLK0_M0/I2S0_SDI3_M0/I2S0_SDO1_M0/GPIO3_A6_d) ; also on sheet 7 10 12
PCIE20_PERSTN_M1: M1.74(PCIE20_PERSTN_M1/PDM_SDI1_M0/I2S0_SDI1_M0/I2S0_SDO3_M0/GPIO3_B0_d) ; also on sheet 7 10 12
PCIE20_REFCLKN: M1.29(PCIE20_REFCLKN) ; also on sheet 7 10
PCIE20_REFCLKP: M1.28(PCIE20_REFCLKP) ; also on sheet 7 10
PCIE20_WAKEN_M1: M1.73(PCIE20_WAKEN_M1/UART5_RX_M1/PDM_SDI2_M0/I2S0_SDI2_M0/I2S0_SDO2_M0/GPIO3_A7_d) ; also on sheet 7 10 12
PMIC_32KOUT_WIFI: M1.16(PMIC_32KOUT_WIFI) R391.1 ; also on sheet 10 13
PMIC_EXT_EN: M1.8(PMIC_EXT_EN) R4.1 R9.1 ; also on sheet 10
PMIC_PWRON: M1.4(PMIC_PWRON) ; also on sheet 14
PMIC_SLEEP_H: M1.15(PMIC_SLEEP_H_OUT) R1083.1
PMIC_VDC: C302.2 M1.5(PMIC_VDC) R17.1 R389.2
RESETn: M1.6(RESETn) R36.1 ; also on sheet 14
RGMII_CLK_M0: M1.115(CAM_CLK1_OUT_M1/PDM_CLK0_M1/RGMII_CLK_M0/VO_LCDC_CLK/GPIO4_B7_d) ; also on sheet 8
RGMII_MDC_M0: M1.110(UART9_TX_M0/RGMII_MDC_M0/VO_LCDC_D2/GPIO4_B2_d) ; also on sheet 8
RGMII_MDIO_M0: M1.111(UART9_RX_M0/RGMII_MDIO_M0/VO_LCDC_D18/GPIO4_B3_d) ; also on sheet 8
RGMII_RXCLK_M0: M1.101(I2S2_LRCK_M1/PWM12_M0/RGMII_RXCLK_M0/VO_LCDC_D21/GPIO4_A1_d) ; also on sheet 8
RGMII_RXD0_M0: M1.105(I2C3_SCL_M1/PDM_SDI2_M1/UART1_TX_M1/RGMII_RXD0_M0/VO_LCDC_D1/GPIO4_A5_d) ; also on sheet 8
RGMII_RXD1_M0: M1.106(I2C3_SDA_M1/PDM_SDI3_M1/UART1_RX_M1/RGMII_RXD1_M0/VO_LCDC_D8/GPIO4_A6_d) ; also on sheet 8
RGMII_RXD2_M0: M1.99(SPI1_CSN0_M0/UART8_CTSN_M1/RGMII_RXD2_M0/VO_LCDC_D19/GPIO3_D7_d) ; also on sheet 8
RGMII_RXD3_M0: M1.100(SPI1_CSN1_M0/UART8_RTSN_M1/RGMII_RXD3_M0/VO_LCDC_D20/GPIO4_A0_d) ; also on sheet 8
RGMII_RXDV_M0: M1.107(UART6_TX_M1/PDM_SDI0_M1/UART1_RTSN_M1/RGMII_RXDV_M0/VO_LCDC_D9/GPIO4_A7_d) ; also on sheet 8
RGMII_TXCLK_M0: M1.98(I2S2_MCLK_M1/SPI1_CLK_M0/RGMII_TXCLK_M0/VO_LCDC_D15/GPIO3_D6_d) ; also on sheet 8
RGMII_TXD0_M0: M1.102(UART6_CTSN_M1/SPI1_MOSI_M0/RGMII_TXD0_M0/VO_LCDC_D22/GPIO4_A2_d) ; also on sheet 8
RGMII_TXD1_M0: M1.103(UART6_RTSN_M1/SPI1_MISO_M0/RGMII_TXD1_M0/VO_LCDC_D23/GPIO4_A3_d) ; also on sheet 8
RGMII_TXD2_M0: M1.96(I2S2_SDI_M1/UART8_TX_M1/RGMII_TXD2_M0/VO_LCDC_D13/GPIO3_D4_d) ; also on sheet 8
RGMII_TXD3_M0: M1.97(I2S2_SDO_M1/UART8_RX_M1/RGMII_TXD3_M0/VO_LCDC_D14/GPIO3_D5_d) ; also on sheet 8
RGMII_TXEN_M0: M1.104(PWM13_M0/RGMII_TXEN_M0/VO_LCDC_D0/GPIO4_A4_d) ; also on sheet 8
RMII_CLK: M1.36(RMII_CLK/SPI2_CSN1_M1/UART4_RX_M1/RGMII_CLK_M1/I2S2_SCLK_M0/GPIO1_D5_d) ; also on sheet 11
RMII_CRS_DV: M1.35(RMII_RXDV_CRS/SPI2_CSN0_M1/UART4_TX_M1/RGMII_RXDV_M1/I2S2_LRCK_M0/GPIO1_D6_d) ; also on sheet 11
RMII_MDC: M1.42(RMII_MDC/PWM2_M1/I2C5_SCL_M1/RGMII_MDC_M1/SDMMC1_PWREN/GPIO1_C7_d) ; also on sheet 11
RMII_MDIO: M1.41(RMII_MDIO/PWM3_M1/I2C5_SDA_M1/RGMII_MDIO_M1/SDMMC1_DETN/GPIO1_D0_d) ; also on sheet 11
RMII_RSTn: M1.32(CLK1_32K_OUT/SPI2_CLK_M1/I2S0_SDO3_M1/ETH_CLK_25M_OUT_M1/I2S2_MCLK_M0/GPIO2_A1_d) ; also on sheet 11
RMII_RXD0: M1.37(RMII_RXD0/PWM7_M1/I2S0_SDI3_M1/RGMII_RXD0_M1/UART1_CTSN_M0/GPIO1_D4_d) ; also on sheet 11
RMII_RXD1: M1.34(RMII_RXD1/PWM14_M1/SPI2_MOSI_M1/UART4_RTSN_M1/RGMII_RXD1_M1/I2S2_SDO_M0/GPIO1_D7_d) ; also on sheet 11
RMII_RXER: M1.33(RMII_RXER/PWM15_M1/SPI2_MISO_M1/UART4_CTSN_M1/RGMII_RXER_M1/I2S2_SDI_M0/GPIO2_A0_d) ; also on sheet 11
RMII_TXD0: M1.40(RMII_TXD0/PWM4_M1/I2S0_SDO1_M1/RGMII_TXD0_M1/UART1_RX_M0/GPIO1_D1_d) ; also on sheet 11
RMII_TXD1: M1.39(RMII_TXD1/PWM5_M1/I2S0_SDO2_M1/RGMII_TXD1_M1/UART1_TX_M0/GPIO1_D2_d) ; also on sheet 11
RMII_TXEN: M1.38(RMII_TXEN/PWM6_M1/I2S0_SDI2_M1/RGMII_TXEN_M1/UART1_RTSN_M0/GPIO1_D3_d) ; also on sheet 11
SARADC0_BOOT: M1.179(SARADC0_BOOT) R1202.1
SARADC0_IN1_KEY/RECOVERY: M1.56(SARADC0_IN1_KEY/RECOVERY) ; also on sheet 14
SARADC0_IN3: M1.57(SARADC0_IN3)
SARADC0_IN4: M1.58(SARADC0_IN4)
SARADC0_IN5: M1.59(SARADC0_IN5)
SARADC0_IN6: M1.60(SARADC0_IN6)
SARADC0_IN7: M1.61(SARADC0_IN7)
SARADC1_IN0: C272.2 M1.62(SARADC1_IN0) ; also on sheet 9
SARADC1_IN1: C273.2 M1.63(SARADC1_IN1) ; also on sheet 9
SARADC1_IN2: C274.2 M1.64(SARADC1_IN2) ; also on sheet 9
SARADC1_IN3: C275.2 M1.65(SARADC1_IN3) ; also on sheet 9
SARADC1_IN4: C276.2 M1.66(SARADC1_IN4) ; also on sheet 9
SARADC1_IN5: C277.2 M1.67(SARADC1_IN5) ; also on sheet 9
SARADC1_IN6: M1.68(SARADC1_IN6)
SARADC1_IN7: M1.69(SARADC1_IN7)
SD_CD: J6.9(CD) R28.2
SD_CLK: C279.2 J6.5(CLK) R25.2
SDMMC0_CLK: M1.51(SPI1_CLK_M1/UART5_TX_M0/TEST_CLK_OUT/SDMMC0_CLK/CAN1_TX_M0/GPIO1_C0_d) R25.1
SDMMC0_CMD: J6.3(CMD) M1.52(SPDIF_TX_M2/UART5_RX_M0/SDMMC0_CMD/CAN1_RX_M0/GPIO1_B7_u)
SDMMC0_D0: J6.7(DATA0) M1.50(DSM_AUD_LP/SPI1_MOSI_M1/UART7_RX_M1/UART0_RX_M1/SDMMC0_D0/GPIO1_B3_u)
SDMMC0_D1: J6.8(DATA1) M1.49(DSM_AUD_LN/SPI1_MISO_M1/UART7_TX_M1/UART0_TX_M1/SDMMC0_D1/GPIO1_B4_u)
SDMMC0_D2: J6.1(DATA2) M1.54(DSM_AUD_RP/PWM10_M0/SPI1_CSN1_M1/UART5_CTSN_M0/JTAG_CPU_MCU_TCK_M1/SDMMC0_D2/GPIO1_B5_u)
SDMMC0_D3: J6.2(CD/DATA3) M1.53(DSM_AUD_RN/PWM11_M0/SPI1_CSN0_M1/UART5_RTSN_M0/JTAG_CPU_MCU_TMS_M1/SDMMC0_D3/GPIO1_B6_u)
SDMMC0_DET_L: M1.171(I2C4_SDA_M1/SDMMC0_DETN/GPIO0_A4_u) R28.1 R431.2
SDMMC1_CLK: M1.43(PWM1_M1/I2S0_MCLK_M1/RGMII_RXCLK_M1/SDMMC1_CLK/GPIO1_C6_d) ; also on sheet 13
SDMMC1_CMD: M1.44(PWM0_M1/I2S0_SCLK_M1/RGMII_RXD3_M1/SDMMC1_CMD/GPIO1_C5_d) ; also on sheet 13
SDMMC1_D0: M1.48(PWM8_M1/I2S0_SDI0_M1/RGMII_TXD2_M1/SDMMC1_D0/GPIO1_C1_d) ; also on sheet 13
SDMMC1_D1: M1.47(PWM9_M1/I2S0_SDI1_M1/RGMII_TXD3_M1/SDMMC1_D1/GPIO1_C2_d) ; also on sheet 13
SDMMC1_D2: M1.46(PWM10_M1/I2S0_SDO0_M1/RGMII_TXCLK_M1/SDMMC1_D2/GPIO1_C3_d) ; also on sheet 13
SDMMC1_D3: M1.45(PWM11_M1/I2S0_LRCK_M1/RGMII_RXD2_M1/SDMMC1_D3/GPIO1_C4_d) ; also on sheet 13
SIM_CLK: C62.2 J11.C3(CLK) R55.2 U8.6(CLK)
SIM_DATA: C63.2 J11.C7(DATA) R53.1 R54.2 U8.3(I/O)
SIM_RST: C61.2 J11.C2(RESET) R56.2 R440.1 U8.7(RST)
SNSN: M1.178(SNSN) TP1.1
SNSP: M1.177(SNSP) TP2.1
SPI0_CLK_M0: M1.160(SPI0_CLK_M0/PWM0_M0/UART2_RTSN_M0/GPIO0_C3_d) ; also on sheet 9
SPI0_CSN0_M0: M1.159(SPI0_CSN0_M0/PWM5_M0/UART2_CTSN_M0/GPIO0_C2_d) ; also on sheet 9
SPI0_MISO_M0: M1.162(SPI0_MISO_M0/PWM2_M0/UART6_RTSN_M0/GPIO0_C5_d) ; also on sheet 9
SPI0_MOSI_M0: M1.161(SPI0_MOSI_M0/PWM1_M0/UART6_CTSN_M0/GPIO0_C4_d) ; also on sheet 9
SPK_EN_H_GPIO4_B6_d: M1.114(UART3_CTSN_M0/SPI2_CLK_M0/I2S1_SDO3_M0/VO_LCDC_DEN/GPIO4_B6_d) ; also on sheet 12
SPKN_OUT: M1.175(SPKN_OUT) TP5.1
SPKP_OUT: M1.174(SPKP_OUT) TP4.1
SYS_LED_H: R21.1 R415.2 R1173.1
TP_INT: J13.3 R449.1 U59.4(A3)
TP_INT_L_GPIO0_B6_d: M1.156(PCIE20_WAKEN_M0/I2C2_SDA_M0/GPIO0_B6_d) U59.8(B3)
TP_RST: J13.2 U59.5(A4)
TP_RST_L_GPIO0_B5_d: M1.155(PCIE20_PERSTN_M0/I2C2_SCL_M0/GPIO0_B5_d) U59.7(B4)
TP_SCL: J13.4 R422.1 U59.3(A2)
TP_SDA: J13.5 R421.1 U59.2(A1)
UART0_RX_M0_DEBUG: M1.165(JTAG_CPU_MCU_TMS_M0/UART0_RX_M0/GPIO0_D0_u) ; also on sheet 14
UART0_TX_M0_DEBUG: M1.166(JTAG_CPU_MCU_TCK_M0/UART0_TX_M0/GPIO0_D1_u) ; also on sheet 14
UART3_CTSN_M1: M1.82(I2C4_SCL_M0/SPI0_CSN1_M1/UART3_CTSN_M1/I2S1_SDI3_M1/I2S1_SDO1_M1/CAN0_TX_M1/GPIO3_B6_d) ; also on sheet 13
UART3_RTSN_M1: M1.79(UART3_RTSN_M1/ISP_FLASH_TRIGIN/I2S1_SDI0_M1/GPIO3_C1_d) ; also on sheet 13
UART3_RX_M1: M1.80(SPI0_MISO_M1/UART3_RX_M1/I2S1_SDI1_M1/I2S1_SDO3_M1/GPIO3_C0_d) ; also on sheet 13
UART3_TX_M1: M1.81(I2C4_SDA_M0/SPI0_CSN0_M1/UART3_TX_M1/I2S1_SDI2_M1/I2S1_SDO2_M1/CAN0_RX_M1/GPIO3_B7_d) ; also on sheet 13
UART4_RX_M0: M1.92(UART3_RTSN_M0/UART4_RX_M0/I2S1_SDI1_M0/VO_LCDC_D10/GPIO3_D1_d) ; also on sheet 9
UART4_TX_M0: M1.91(UART4_TX_M0/I2S1_SDI0_M0/VO_LCDC_D7/GPIO3_D0_d) ; also on sheet 9
UART6_RX_M0: M1.164(UART6_RX_M0/CAN0_RX_M2/GPIO0_C7_d) ; also on sheet 9
UART6_TX_M0: M1.163(UART6_TX_M0/CAN0_TX_M2/GPIO0_C6_d) ; also on sheet 9
UART8_RX_M0: M1.85(UART8_RX_M0/CAM_CLK1_OUT_M0/I2S1_SCLK_M1/GPIO3_B3_d) ; also on sheet 9
UART8_TX_M0: M1.86(UART8_TX_M0/CAM_CLK0_OUT_M0/I2S1_MCLK_M1/GPIO3_B2_d) ; also on sheet 9
UART9_RX_M1: M1.77(I2C5_SDA_M0/UART9_RX_M1/ISP_FLASH_TRIGOUT/GPIO3_C3_d) ; also on sheet 9
UART9_TX_M1: M1.78(I2C5_SCL_M0/UART9_TX_M1/ISP_PRELIGHT_TRIGOUT/GPIO3_C2_d) ; also on sheet 9
USB20_HOST1_DM: M1.22(USB20_HOST1_DM) U7.30(DMU)
USB20_HOST1_DP: M1.23(USB20_HOST1_DP) U7.31(DPU)
USB30_OTG0_DM: M1.18(USB30_OTG0_DM) ; also on sheet 10
USB30_OTG0_DP: M1.19(USB30_OTG0_DP) ; also on sheet 10
USB30_OTG0_ID: M1.20(USB30_OTG0_ID) ; also on sheet 10
USB30_OTG0_SSRXN/PCIE20_RXDN: M1.27(USB30_OTG0_SSRXN/PCIE20_RXDN) ; also on sheet 10
USB30_OTG0_SSRXP/PCIE20_RXDP: M1.26(USB30_OTG0_SSRXP/PCIE20_RXDP) ; also on sheet 10
USB30_OTG0_SSTXN/PCIE20_TXDN: M1.25(USB30_OTG0_SSTXN/PCIE20_TXDN) ; also on sheet 10
USB30_OTG0_SSTXP/PCIE20_TXDP: M1.24(USB30_OTG0_SSTXP/PCIE20_TXDP) ; also on sheet 10
USB30_OTG0_VBUSDET: M1.21(USB30_OTG0_VBUSDET) ; also on sheet 10
USB_HOST3_PWREN_H: R430.1 R450.1 U4.4(EN)
USB_HOST4_PWREN_H: R451.1 R1082.1 U5.4(EN)
USB_OTG_DET_GPIO0_C0_d: M1.158(GPU_AVS/PWM7_M0/UART2_TX_M0/CAN1_TX_M1/GPIO0_C0_d) ; also on sheet 10
USB_OTG_PWREN: R429.1 ; also on sheet 10
USIM_CLK: J10.12(USIM_CLK) R55.1
WIFI_REG_ON_H_GPIO0_A0_d: M1.172(REF_CLK_OUT/GPIO0_A0_d) ; also on sheet 13
N19487510: C84.1 Q3.1(GATE) R80.1 R443.2
N19487520: Q4.3(DRAIN) R443.1
N69227900: L3.1 U3.3(SW)
N69227918: C31.1 R8.1 R10.2 U3.5(FB)
N69724413: C37.2 R9.2 U3.1(EN)
N69763264: C1049.1 M1.14(MIC1_IN)
N69763270: C1050.1 M1.13(MIC2_IN)
N69764395: J10.10(USIM_IO) R54.1
N69764397: J10.14(USIM_RESET) R56.1
N69764433: LED2.A(ANODE) R452.1
N69764492: R441.2 U9.1(EN)
N69764501: C79.1 R60.1 R442.2 U9.5(FB)
N69764515: L7.1 U9.3(SW)
N69764582: J10.8(VREG_USIM) R52.1
N69765778: R31.1 U4.3(OCB)
N69765789: R34.1 U5.3(OCB)
N69765908: R439.1 U7.48(OVCB_1)
N69765931: R438.1 U7.36(BUS_B)
N69765961: R435.2 U7.5(OVCB_3)
N69765963: R436.2 U7.7(OVCB_4)
N69791555: R434.2 U7.1(OVCB_2)
N69811283: D18.A L8.2 U10.1(LX)
N69811295: R84.1 U10.3(FB)
N69814289: LED1.1(+) R19.2
N69814308: LED1.2(-) Q1.3(DRAIN)
N69814328: Q1.1(GATE) R21.2
N69841804: D1.A D2.A D3.C F3.2 F4.2
N69861791: C82.2 J13.1 R62.2
N70088511: R448.1 U59.12(OE)
N70100637: R414.1 U7.42(DRV)
N70140073: Q4.1(GATE) R453.2
N70164941: R787.2 R1060.1 R1061.2 U70.9(FB)
N70165129: R782.2 R783.2 U70.12(EN)
N70165139: C810.1 U70.7(BS)
N70165141: C810.2 L33.1 U70.2(LX)
N70165164: C815.2 R1061.1
N70166760: C1012.1 Q8.1(GATE) R1062.2 R1063.1
N70166762: Q7.3(DRAIN) R1062.1
N70166881: Q7.1(GATE) R4.2
N70190247: C1034.1 Q10.1(GATE) R1079.2 R1080.1
N70190249: Q9.3(DRAIN) R1079.1 R1083.2
N70190329: Q9.1(GATE) R1078.2 R1192.1
N70208813: C282.2 C283.2 D79.A(I/O2) M1.1(VCC5V0_IN1) M1.2(VCC5V0_IN2) R1209.1 R1210.1
N70209347: C1035.2 J10.22(PERST_N)

Not connected (* = marked no-connect by the designer): J1 1(NC)*; J10 1(MICP)* 3(MICN)* 5(EARP)* 6(NC1)* 7(EARN)* 11(UART1_RX)* 13(UART1_TX)* 16(NC2)* 17(UART1_R1)* 19(WAKEUP_N)* 20(W_DISABLE_N)* 23(UART1_CTS)* 25(UART1_RFR)* 28(NC4)* 30(UART2_RFR)* 31(UART1_DTR)* 32(UART2_CTS)* 33(UART1_DCD)* 44(UART2_RX)* 45(AUX_PCM_CLK)* 46(UART2_TX)* 47(AUX_PCM_DOUT)* 48(NC5)* 49(AUX_PCM_DIN)* 51(AUX_PCM_SYNC)* 53(MT1)* 54(MT2)*; J11 C6(VPP)* CD1* CD2*; J16 4* 19* 20*; LED1 3(E)*; U7 2(PWRB)* 4(PWRB_3)* 8(PWRB_4)* 38(VD5_IN)* 43(LED_1)* 44(LED_2)* 45(LED_3)* 46(LED_4)* 47(PWRB_1)*; U8 2(NC1)* 4(NC3)* 5(NC2)*; U70 11(PG)*

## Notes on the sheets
sheet 1
- DCIN 9-30V
- VDD_5V
- VCC5V_SYS
- 4-28V
- 8A
- VCC_3V3
- Vout=（1+R1/R2）× 0.6V
  EN >= 0.8V
- VCC3V3_SYS
- EN>1.2V
sheet 2
- VDC
- LED
- TF_CARD
sheet 3
- USB HUB-FE1.1
- TO OUT
sheet 4
- SIM_CARD
- ESIM
- 4G/5G_POWER
- VDD_3V8
- Imax:2.5A
- EN>1.2V
sheet 5
- TP COF Connector
- MIPI_DSI_TX
- MIPI/LVDS Connector
- LVDS_TX
- Backlight
